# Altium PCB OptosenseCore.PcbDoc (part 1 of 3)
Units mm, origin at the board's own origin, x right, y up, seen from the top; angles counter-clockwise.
Board outline 65 x 56 mm, 4 copper layers (Top, Signal Layer 1, Power Layer 2, Bottom), stack 0.844 mm thick; 184 components, 119 nets, 728 pads, 633 vias.
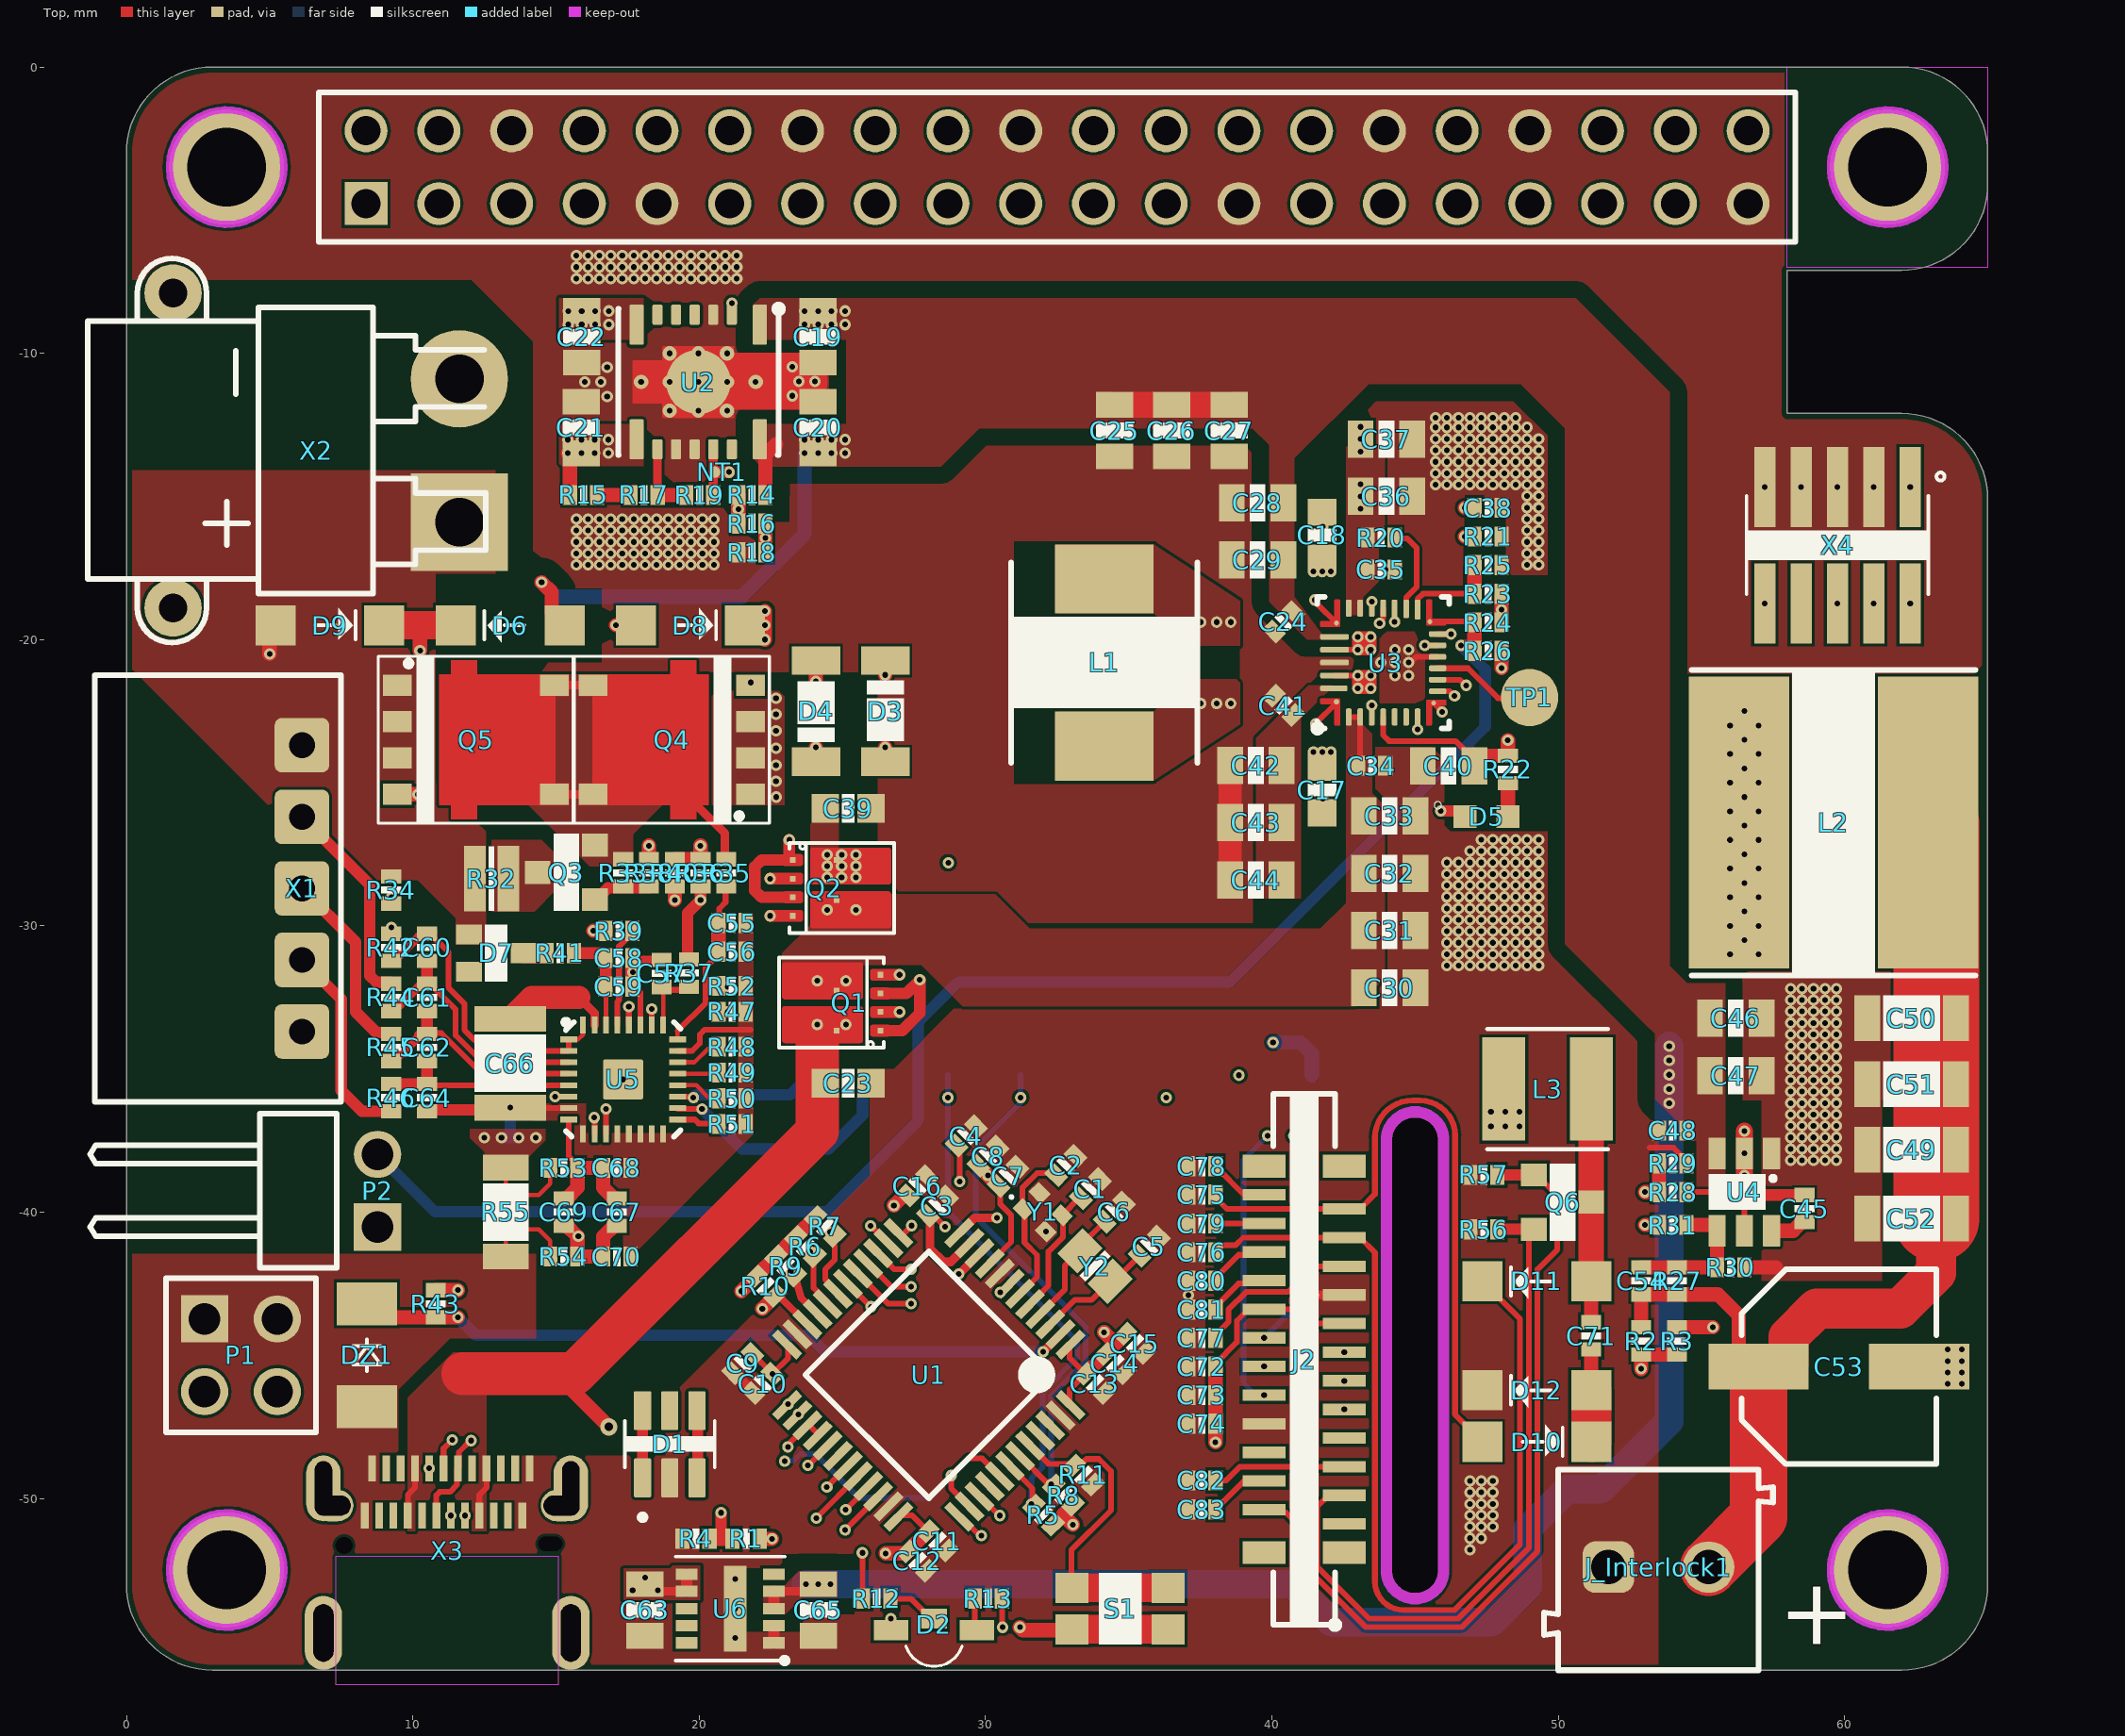
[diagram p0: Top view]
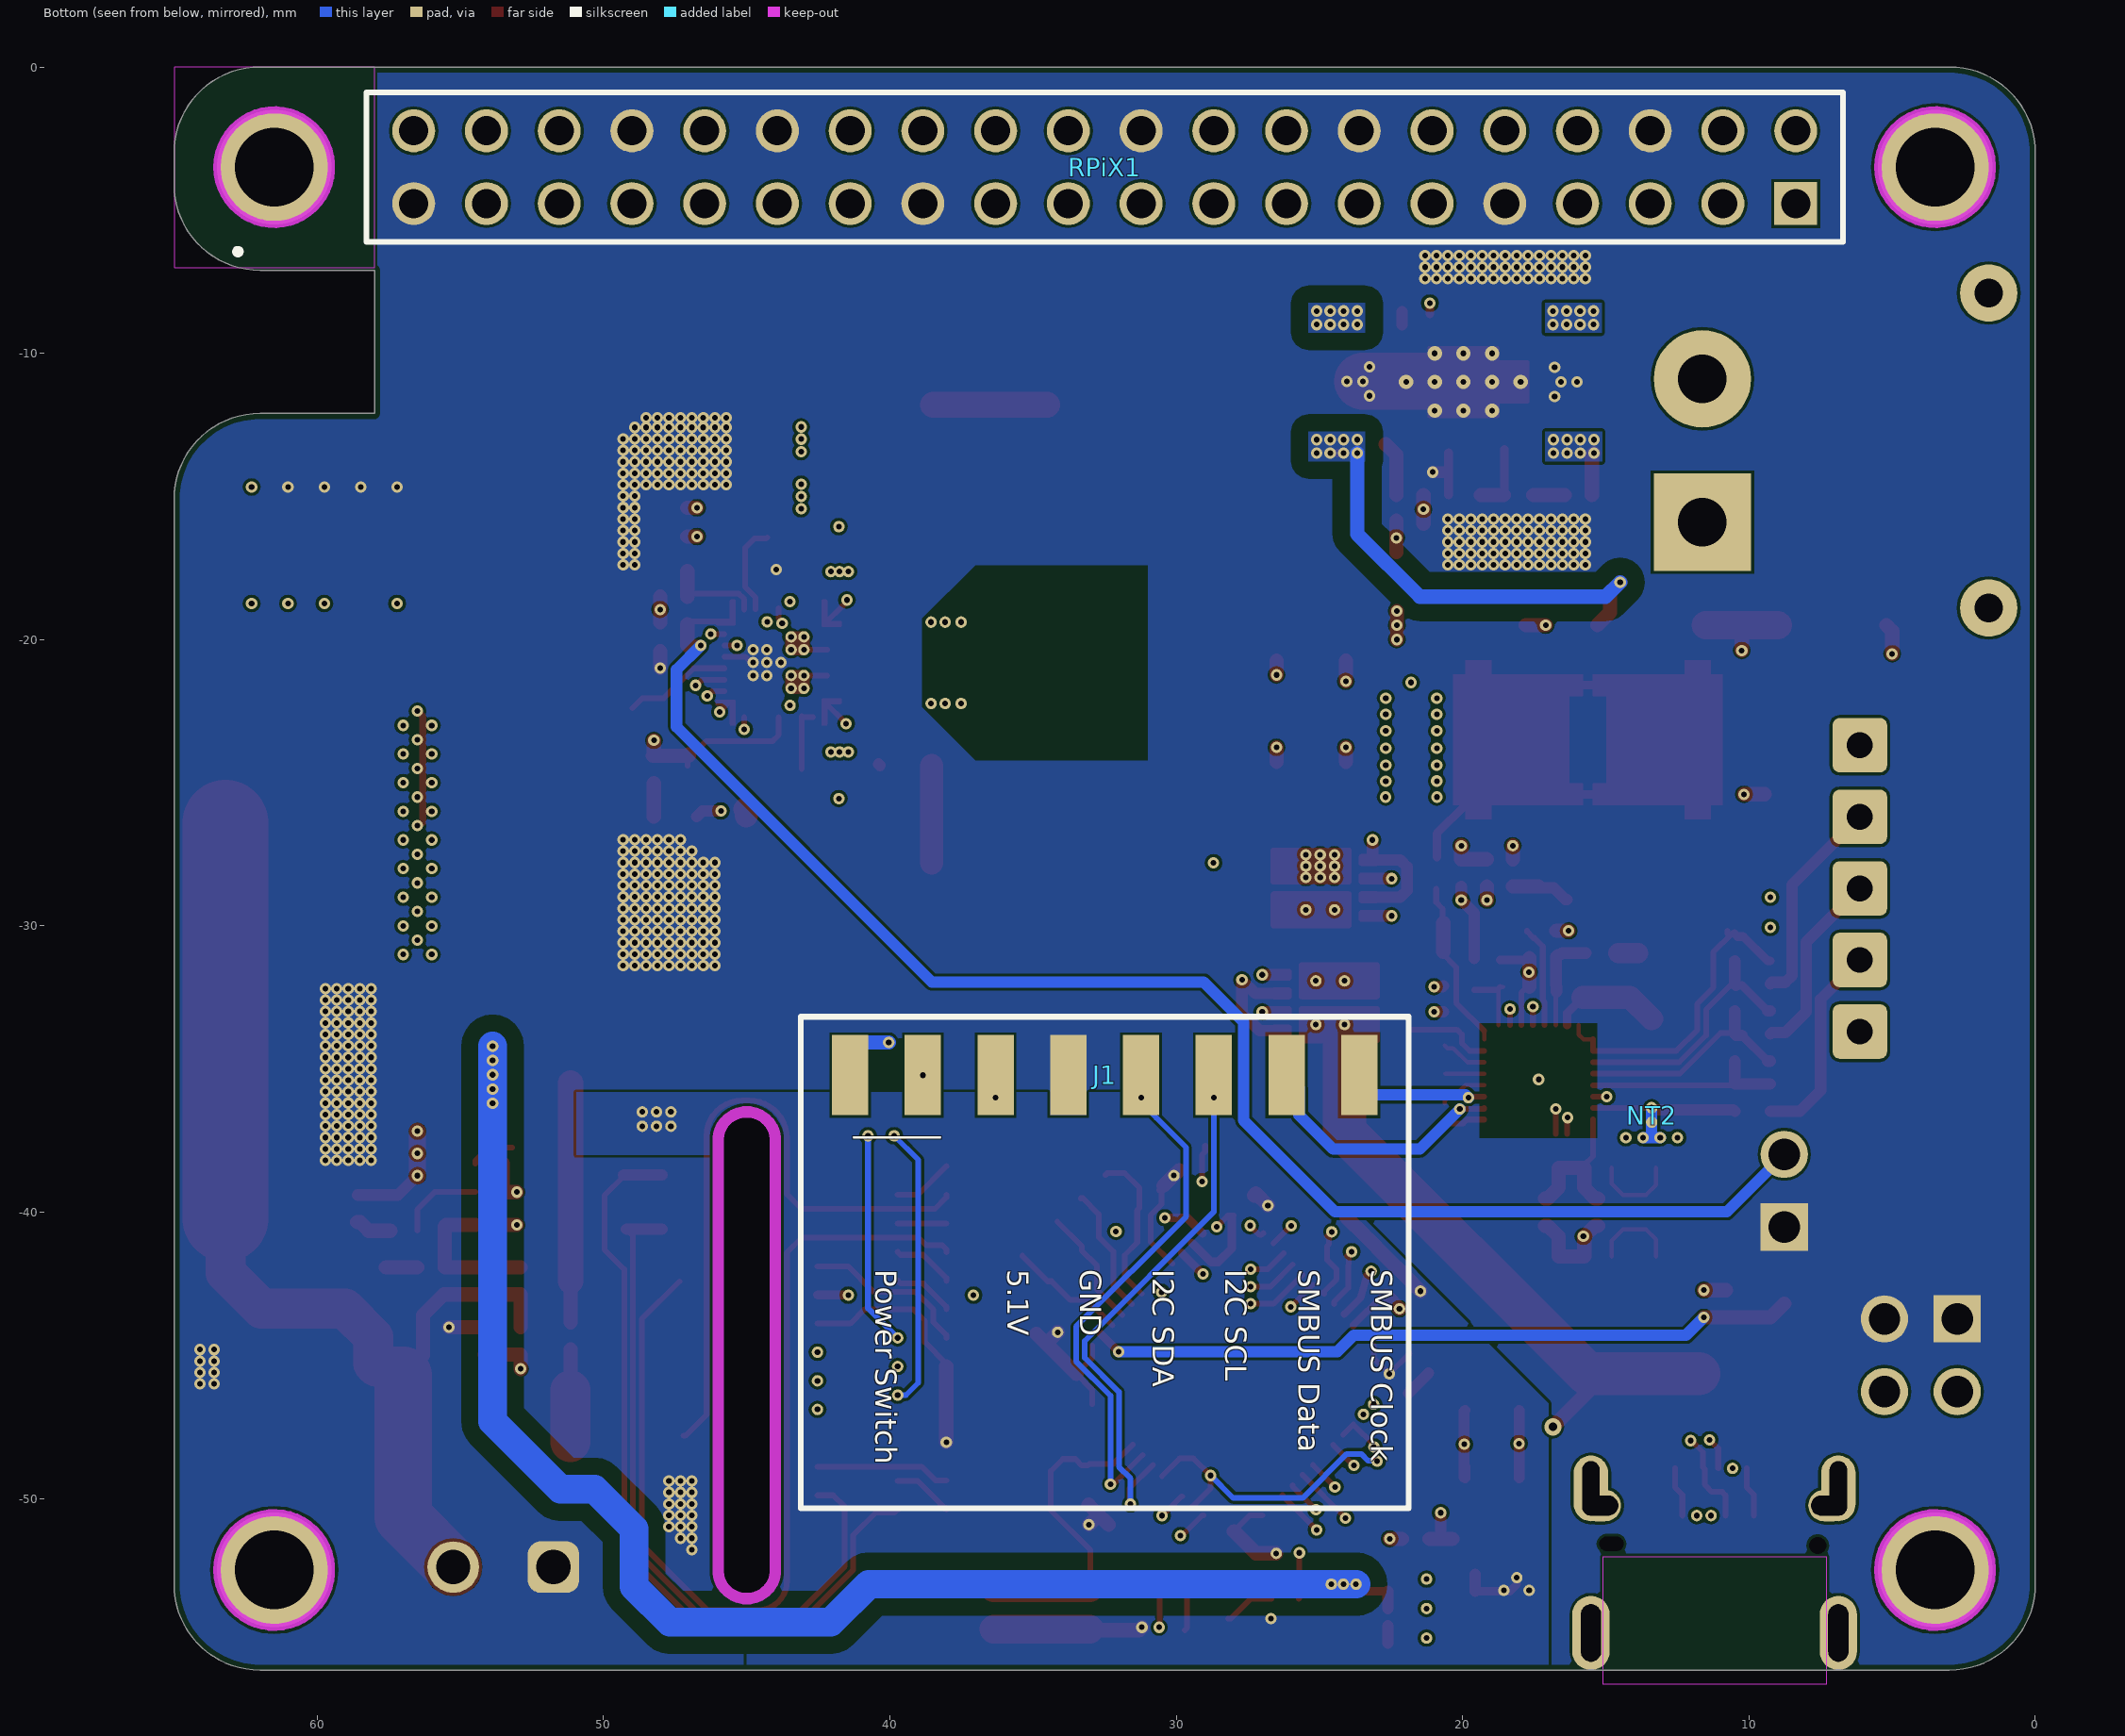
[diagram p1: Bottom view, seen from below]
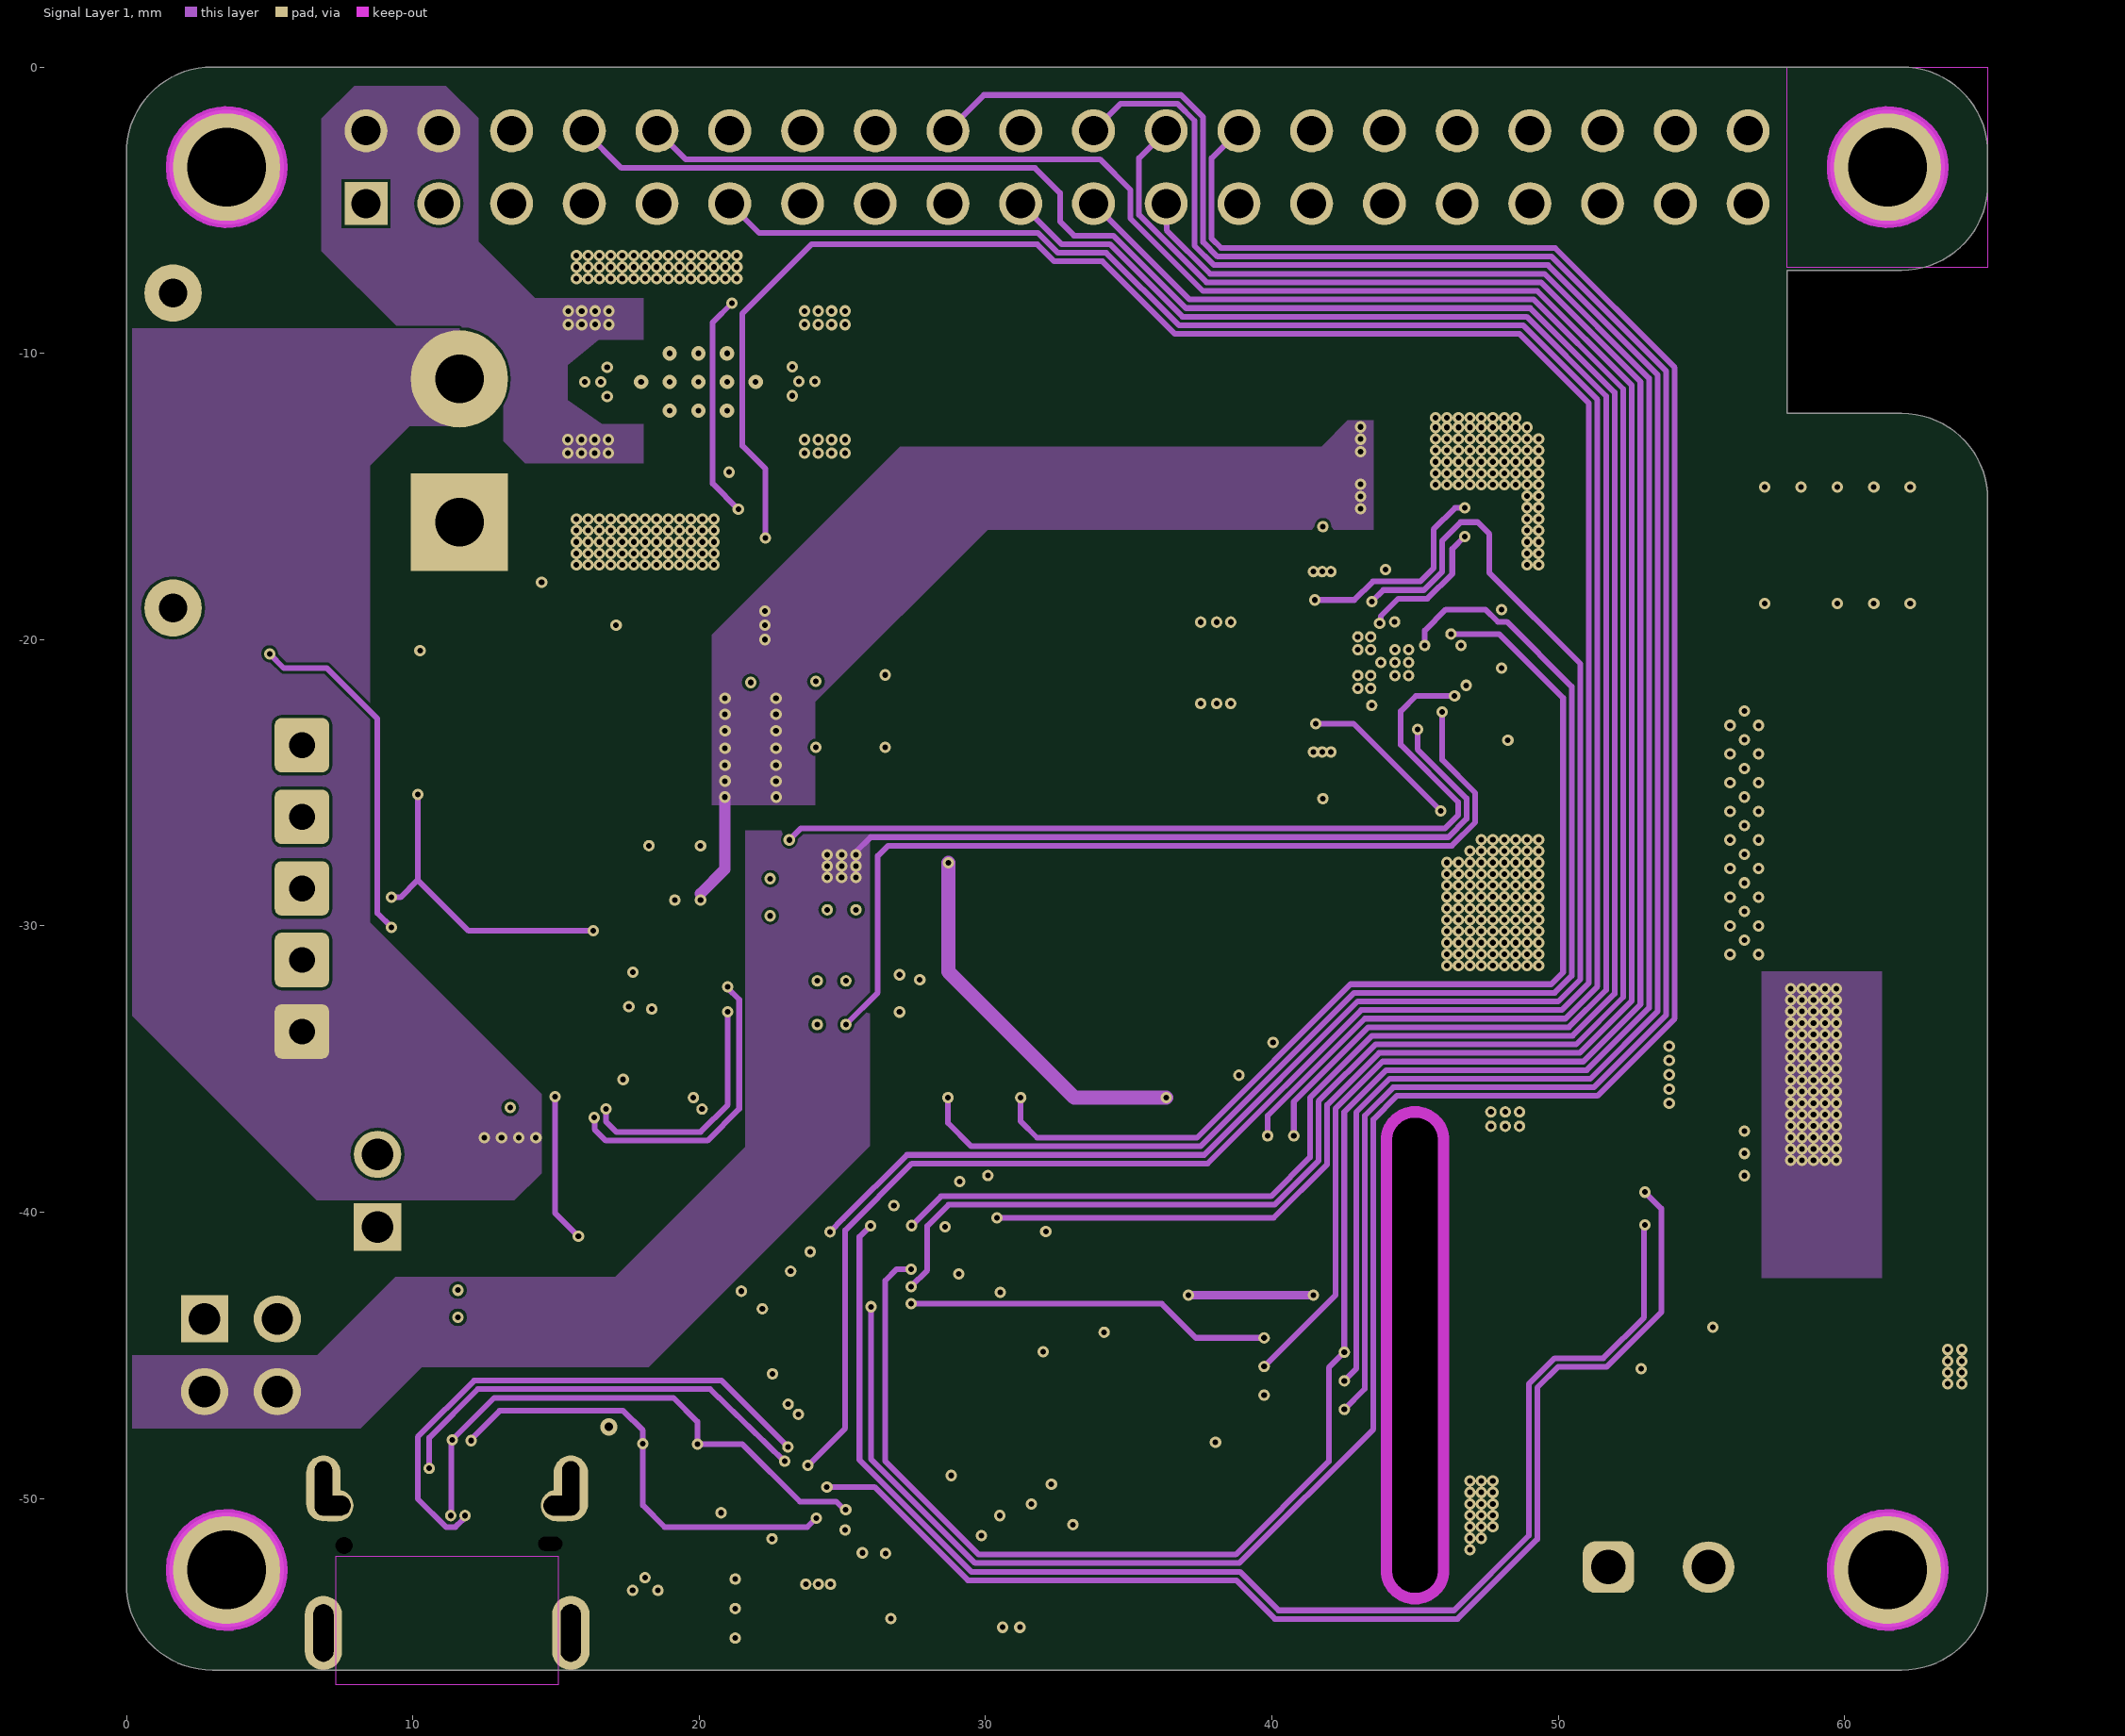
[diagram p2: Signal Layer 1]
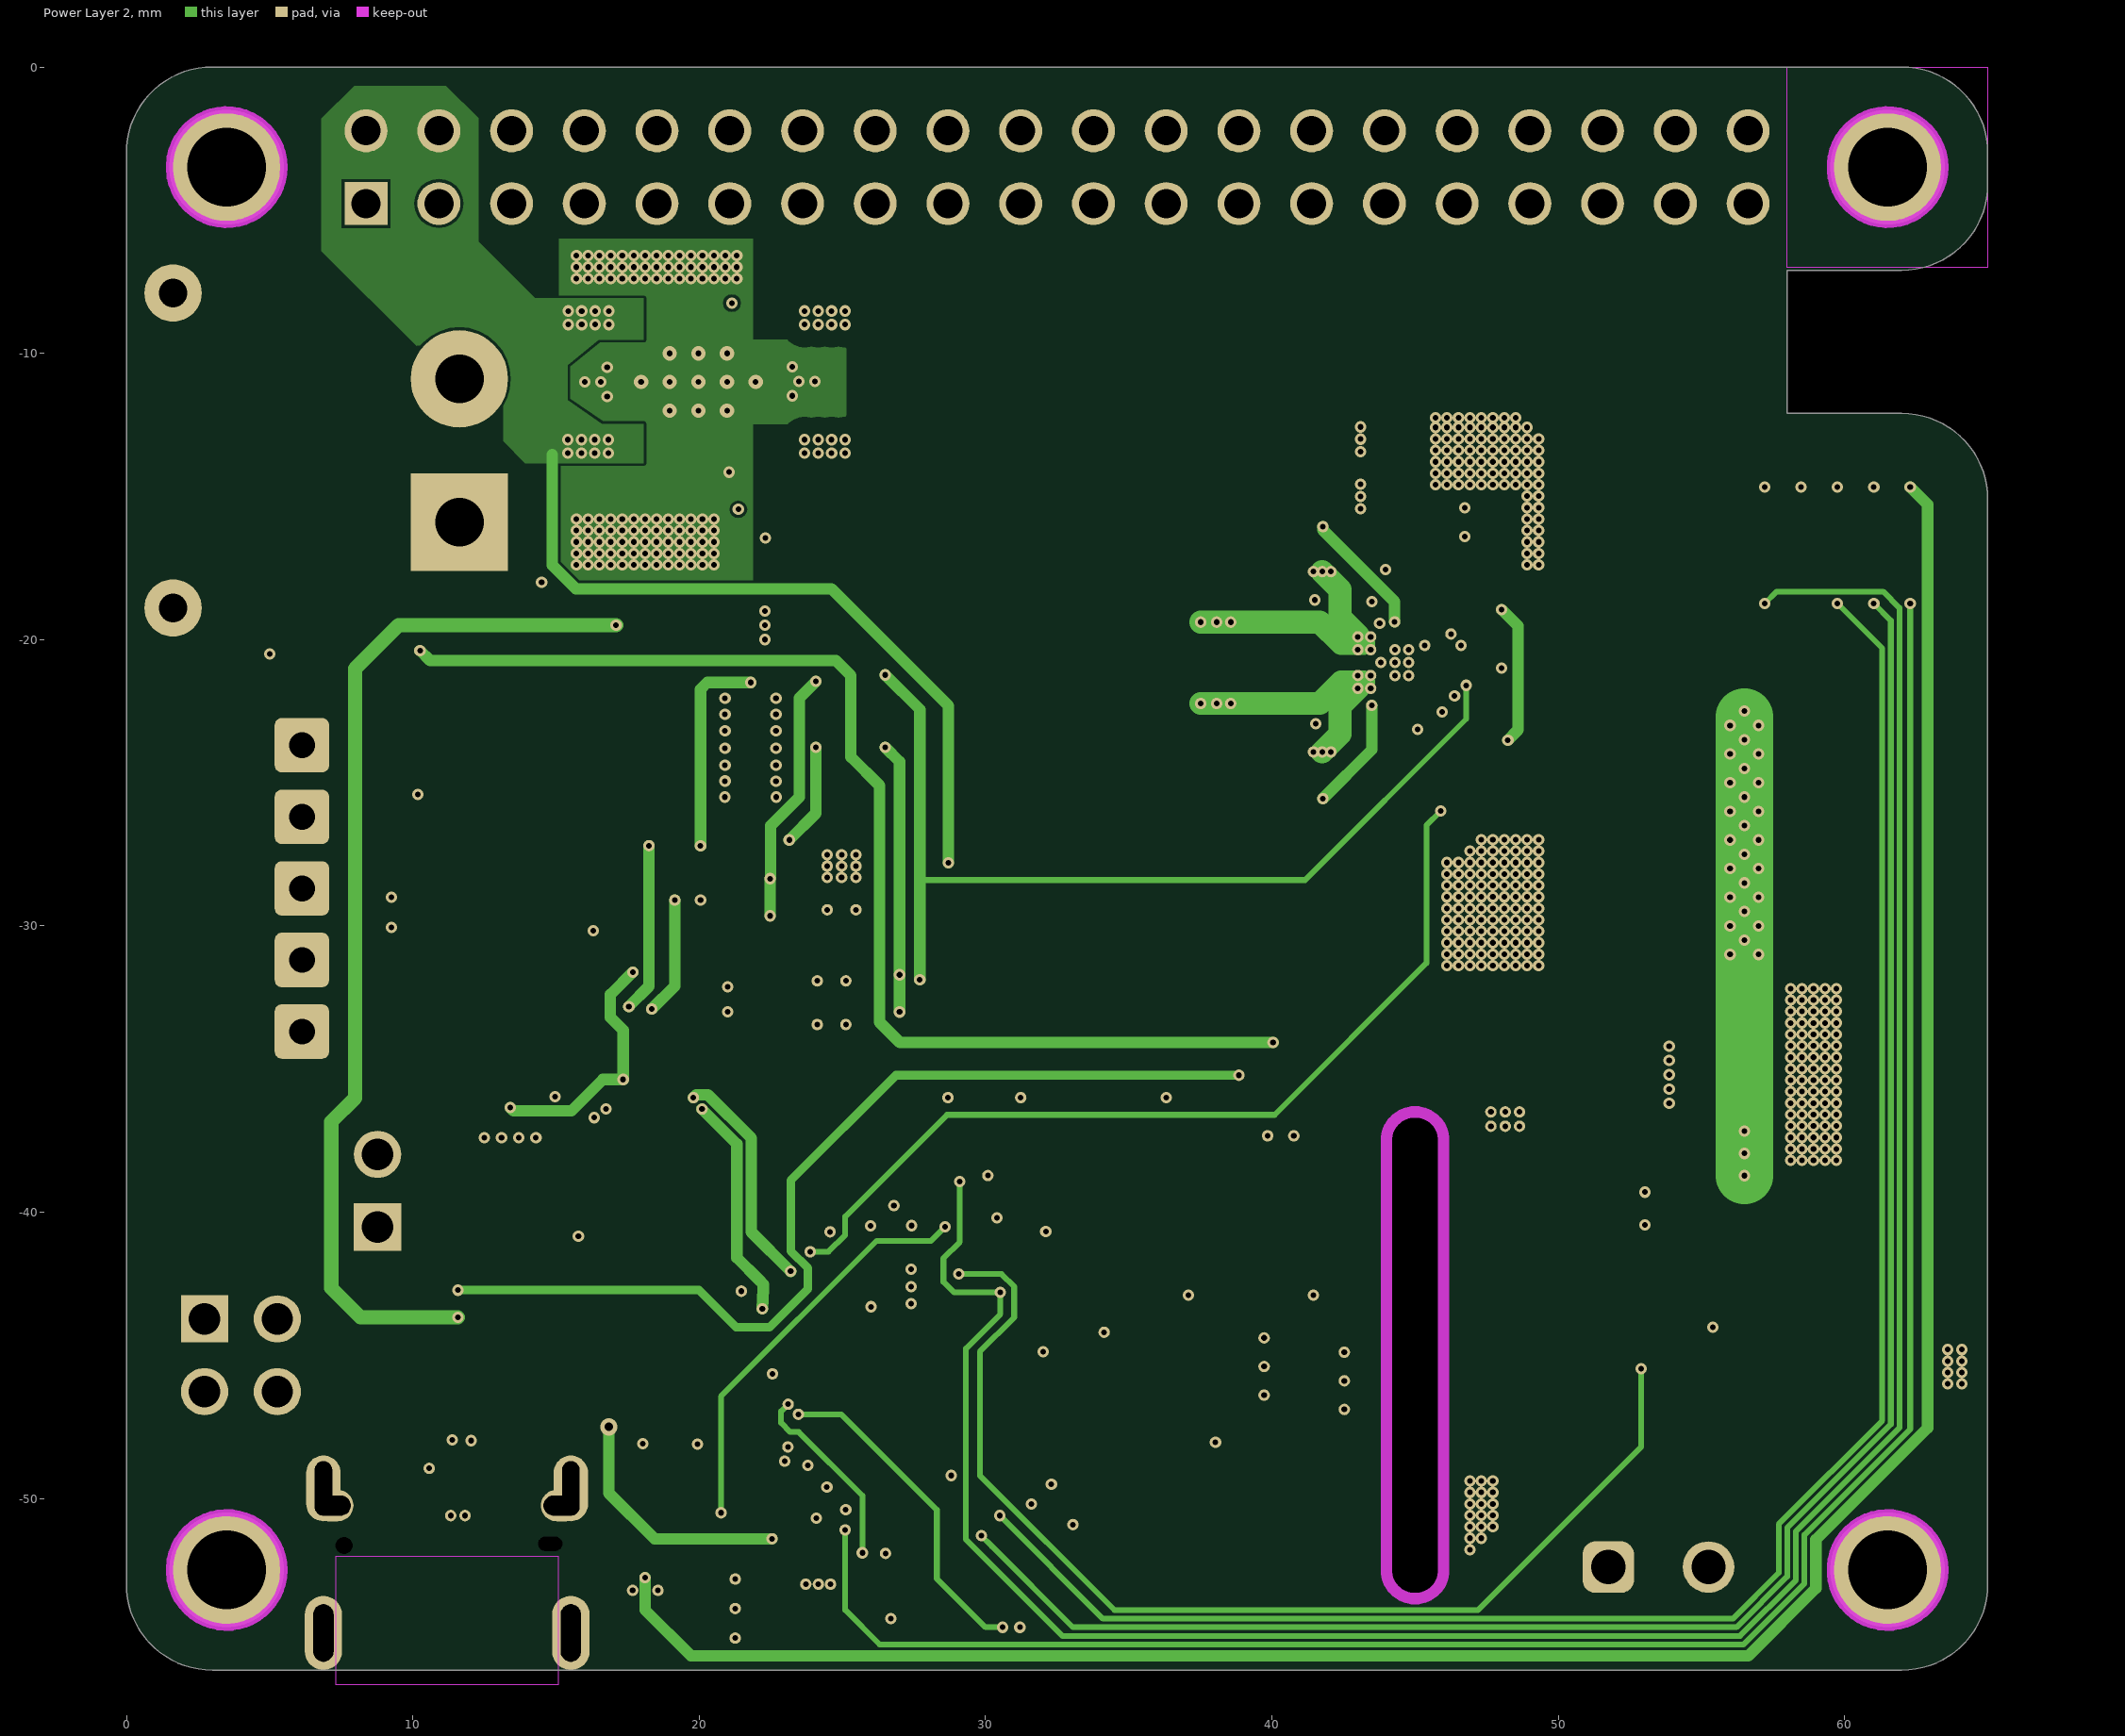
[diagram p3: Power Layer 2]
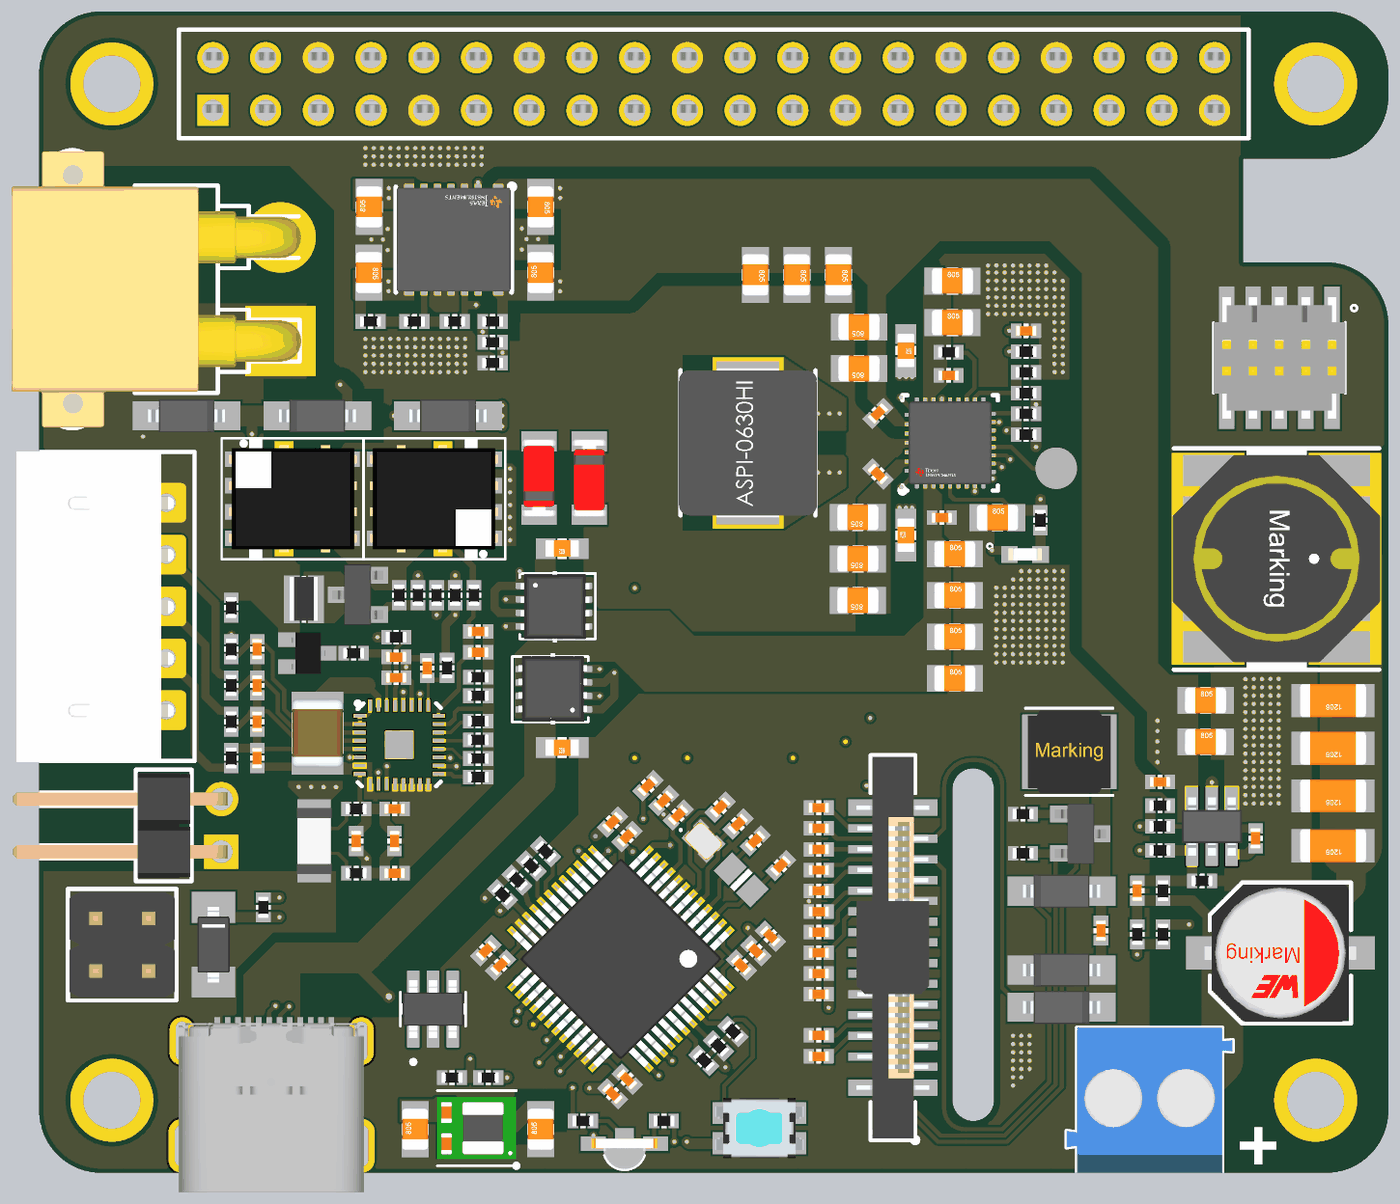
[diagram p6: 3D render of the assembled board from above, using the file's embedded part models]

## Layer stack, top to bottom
Top Solder: solder mask 0.0102, Solder Resist, Dk 3.5
Top: signal copper 0.0356
Dielectric 1: core 0.32, FR-4, Dk 4.8
Signal Layer 1: signal copper 0.036
Dielectric 3: prepreg 0.127, Dk 4.2
Power Layer 2: signal copper 0.036
Dielectric 4: core 0.254, FR-4, Dk 4.2
Bottom: signal copper 0.0356
Bottom Solder: solder mask 0.0102, Solder Resist, Dk 3.5

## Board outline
0,-53 0,-3 cw(c3,-3) 3,0 62,0 cw(c62,-3) 65,-3 65,-4.1 cw(c62,-4.1) 62,-7.1 58,-7.1 58,-12.1 62,-12.1 cw(c62,-15.1) 65,-15.1 65,-53 cw(c62,-53) 62,-56 3,-56 cw(c3,-53)
cut-out: 44,-37.5 cw(c45,-37.5) 45,-36.5 cw(c45,-37.5) 46,-37.5 46,-52.5 cw(c45,-52.5) 45,-53.5 cw(c45,-52.5) 44,-52.5

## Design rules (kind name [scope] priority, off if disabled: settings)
BoardOutlineClearance [All] p1: gap=0.2 ignorepadtopadclearanceinfootprint=FALSE
Clearance Clearance_VSYS [InPolygon vs InNet('VSYS')] p1: gap=0.6 ignorepadtopadclearanceinfootprint=FALSE
Clearance Clearance_2 [All] p2: gap=0.1 ignorepadtopadclearanceinfootprint=FALSE
Clearance Clearance_1 [All] p3: gap=0.1 ignorepadtopadclearanceinfootprint=FALSE
Clearance Clearance_KeepOut [All vs OnLayer('Keep-Out Layer')] p4 off: gap=1 ignorepadtopadclearanceinfootprint=FALSE except(0: Arc-Hole Track-Hole SMDPad-Hole THPad-Hole Via-Hole Fill-Hole Poly-Hole Region-Hole Text-Hole)
Clearance [All] p5: gap=0.1 ignorepadtopadclearanceinfootprint=FALSE
ComponentClearance [All] p1: gap=0 collisioncheckmode=3 verticalgap=0.254 showdistances=FALSE
DiffPairsRouting [All] p1: maxlimit=0.254 minlimit=0.254 mostfreqgap=0.254 toplayer_minwidth=0.381 toplayer_maxwidth=0.381 toplayer_prefwidth=0.381 midlayer1_minwidth=0.381 midlayer1_maxwidth=0.381 midlayer1_prefwidth=0.381 midlayer2_minwidth=0.381 midlayer2_maxwidth=0.381 midlayer2_prefwidth=0.381 bottomlayer_minwidth=0.381 bottomlayer_maxwidth=0.381 bottomlayer_prefwidth=0.381 maxuncoupledlength=12.7
FabricationTestPointUsage TestPointUsage [All] p1: valid=0 allowmultiple=FALSE
FabricationTestpoint Testpoint [All] p1: side=3 testpointundercomponent=TRUE minsize=1.016 maxsize=2.54 preferedsize=1.524 minholesize=0 maxholesize=1.016 preferedholesize=0.813 testpointgrid=0.025 allowsidetop=TRUE allowsidebottom=TRUE usegrid=TRUE gridtolerance=0
HoleSize [All] p1: absolutevalues=TRUE maxlimit=6 minlimit=0.2 maxpercent=80.000 minpercent=20.000
MinimumAnnularRing MinimumAnnularRing_Vias [isVia] p1: minimumring=0.1
MinimumAnnularRing [All] p2: minimumring=0.1
MinimumSolderMaskSliver [All] p1: minsoldermaskwidth=0
NetAntennae [All] p1 off: netantennaetolerance=0
PlaneConnect PlaneConnect_Vias [isVia] p1: planeconnectstyle=Direct reliefexpansion=0.508 reliefentries=4 reliefconductorwidth=0.254 reliefairgap=0.254
PlaneConnect [All] p2: planeconnectstyle=Direct reliefexpansion=0.508 reliefentries=4 reliefconductorwidth=0.254 reliefairgap=0.254
PolygonConnect PolygonConnect_Vias [isVia] p1: connectstyle=Direct reliefconductorwidth=0.254 reliefentries=4 polygonreliefangle="90 Angle" airgapwidth=0.254
PolygonConnect [All] p2: connectstyle=Direct reliefconductorwidth=0.254 reliefentries=4 polygonreliefangle="90 Angle" airgapwidth=0.254
RoutingVias [All] p1: holewidth=0.5 width=0.8 viastyle="Through Hole" minholewidth=0.2 minwidth=0.2 maxholewidth=0.8 maxwidth=1
SMDEntry [All] p1: side=TRUE corner=TRUE anyangle=TRUE
SMDToCorner [All] p1 off: distance=196850
SilkToSilkClearance [All] p1 off: silktosilkclearance=0.15
SilkToSolderMaskClearance SilkscreenOverComponentPads [IsPad] p1 off: minsilkscreentomaskgap=0.15 clearancetoexposedcopper=FALSE
SolderMaskExpansion [All] p1: expansion=0 istentingtop=FALSE
ViasUnderSMD [All] p1: allowed=FALSE
Width [All] p1: maxlimit=10 minlimit=0.15 preferedwidth=0.254 checkconnectedcopper=TRUE
20 further rules are at their usual default settings.

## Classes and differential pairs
net class USB_FS: DIFF_USB_FS_N DIFF_USB_FS_P
component class U_PowerManagement: 23 C17 C18 C19 C20 C21 C22 C23 C24 C25 C26 C27 C28 C29 C30 C31 C32 C33 C34 C35 C36 C37 C38 C39 C40 C41 C42 C43 C44 C45 C46 C47 C48 C49 C50 C51 C52 C53 C54 C55 C56 C57 C58 C59 C60 C61 C62 C63 C64 C65 C66 C67 C68 C69 C70 D3 D4 D5 D6 D7 D8 D9 DZ1 J1 L1 L2 NT1 NT2 P1 P2 Q1 Q2 Q3 Q4 Q5 R2 R3 R14 R15 R16 R17 R18 R19 R20 R21 R22 R23 R24 R25 R26 R27 R28 R29 R30 R31 R32 R33 R34 R35 R36 R37 R38 R39 R40 R41 R42 R43 R44 R45 R46 R47 R48 R49 R50 R51 R52 R53 R54 R55 TP1 U2 U3 U4 U5 U6
component class U_Microcontroller: C1 C2 C3 C4 C5 C6 C7 C8 C9 C10 C11 C12 C13 C14 C15 C16 D1 D2 R1 R4 R5 R6 R7 R8 R9 R10 R11 R12 R13 S1 U1 Y1 Y2
component class U_Connectors: C C71 C72 C73 C74 C75 C76 C77 C78 C79 C80 C81 C82 C83 D10 D11 D12 J2 J_Interlock1 L3 Q6 R56 R57 RPiX1 X1 X2 X3 X4
polygon class Direkt: NETQ4_1_L02_P018
differential pair DIFF_USB_FS: +DIFF_USB_FS_P -DIFF_USB_FS_N

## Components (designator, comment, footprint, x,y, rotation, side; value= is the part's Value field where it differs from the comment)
C1 "10pF" C_0402 33.667,-39.181 r225 top
C2 "10pF" C_0402 32.81,-38.37 r225 top
C3 "2.2uF" C_0402 28.324,-39.784 r225 top
C4 "100nF" C_0402 29.329,-37.338 r225 top
C5 "3.9pF" C_0402 35.716,-41.189 r225 top
C6 "3.9pF" C_0402 34.497,-39.995 r225 top
C7 "100nF" C_0402 30.787,-38.749 r225 top
C8 "1uF" C_0402 30.087,-38.049 r225 top
C9 "100nF" C_0402 21.524,-45.284 r45 top
C10 "1uF" C_0402 22.224,-45.984 r45 top
C11 "4.7uF" C_0402 28.324,-51.484 r135 top
C12 "2.2uF" C_0402 27.624,-52.184 r135 top
C13 "2.2uF" C_0402 33.824,-45.984 r135 top
C14 "100nF" C_0402 34.524,-45.284 r135 top
C15 "2.2uF" C_0402 35.224,-44.584 r135 top
C16 "100nF" C_0402 27.624,-39.084 r225 top
C17 "47nF" C_0603 41.756,-25.257 r90 top
C18 "47nF" C_0603 41.756,-16.352 r270 top
C19 "10uF" C_0805 24.155,-9.423 r270 top
C20 "10uF" C_0805 24.155,-12.592 r90 top
C21 "47uF" C_0805 15.887,-12.592 r270 top
C22 "47uF" C_0805 15.9,-9.423 r90 top
C23 "C_X_0603" C_0603 25.2,-35.5 r180 top
C24 "100nF" C_0402 40.411,-19.38 r45 top
C25 "10uF" C_0805 34.504,-12.7 r270 top
C26 "10uF" C_0805 36.504,-12.7 r270 top
C27 "10uF" C_0805 38.504,-12.7 r270 top
C28 "10uF" C_0805 39.5,-15.224 r180 top
C29 "10uF" C_0805 39.5,-17.224 r180 top
C30 "10uF" C_0805 44.114,-32.163 r0 top
C31 "10uF" C_0805 44.114,-30.163 r0 top
C32 "10uF" C_0805 44.114,-28.163 r0 top
C33 "10uF" C_0805 44.114,-26.163 r0 top
C34 "100nF" C_0402 43.489,-24.409 r180 top
C35 "100nF" C_0402 43.815,-17.551 r180 top
C36 "10uF" C_0805 44,-15 r0 top
C37 "10uF" C_0805 44,-13 r0 top
C38 "1nF" C_0402 47.55,-15.4 r180 top
C39 "C_X_0603" C_0603 25.2,-25.9 r180 top
C40 "4.7uF" C_0805 46.173,-24.409 r0 top
C41 "100nF" C_0402 40.411,-22.303 r315 top
C42 "10uF" C_0805 39.442,-24.397 r180 top
C43 "10uF" C_0805 39.442,-26.397 r180 top
C44 "10uF" C_0805 39.442,-28.397 r180 top
C45 "100nF" C_0402 58.6,-39.875 r90 top
C46 "10uF" C_0805 56.2,-33.227 r0 top
C47 "10uF" C_0805 56.2,-35.227 r0 top
C48 "100nF" C_0402 54,-37.15 r0 top
C49 "22uF" C_1206 62.34,-37.827 r180 top
C50 "22uF" C_1206 62.34,-33.227 r180 top
C51 "22uF" C_1206 62.34,-35.527 r180 top
C52 "22uF" C_1206 62.34,-40.227 r180 top
C53 "47uF" WCAP-ASLI_D6.3H5.5 59.8,-45.4 r180 top
C54 "75pF" C_0402 52.9,-42.4 r270 top
C55 "100pF" C_0402 21.15,-29.9 r0 top
C56 "100pF" C_0402 21.15,-30.9 r0 top
C57 "10nF" C_0402 18.689,-31.662 r270 top
C58 "100pF" C_0402 17.2,-31.125 r0 top
C59 "100pF" C_0402 17.2,-32.125 r0 top
C60 "100nF" C_0402 10.5,-30.75 r90 top
C61 "100nF" C_0402 10.5,-32.5 r90 top
C62 "100nF" C_0402 10.5,-34.25 r90 top
C63 "47uF" C_0805 18.11,-53.897 r90 top
C64 "100nF" C_0402 10.5,-36 r90 top
C65 "10uF" C_0805 24.165,-53.897 r90 top
C66 "2.2uF" C_1210 13.4,-34.8 r90 top
C67 "100pF" C_0402 17.125,-40 r270 top
C68 "100nF" C_0402 17.125,-38.45 r180 top
C69 "100nF" C_0402 15.275,-40 r270 top
C70 "100nF" C_0402 17.125,-41.55 r0 top
C71 "100nF" C_0402 51.153,-44.322 r270 top
C72 "100nF" C_0402 37.557,-45.39 r0 top
C73 "1uF" C_0402 37.557,-46.39 r0 top
C74 "2.2uF" C_0402 37.557,-47.39 r0 top
C75 "1uF" C_0402 37.557,-39.387 r0 top
C76 "1uF" C_0402 37.557,-41.4 r0 top
C77 "1uF" C_0402 37.557,-44.39 r0 top
C78 "1uF" C_0402 37.557,-38.396 r0 top
C79 "1uF" C_0402 37.557,-40.4 r0 top
C80 "1uF" C_0402 37.557,-42.4 r0 top
C81 "1uF" C_0402 37.557,-43.4 r0 top
C82 "1uF" C_0402 37.557,-49.369 r0 top
C83 "1uF" C_0402 37.557,-50.385 r0 top
D1 "USBLC6-2SC6" SOT95P280X145-6N 18.974,-48.108 r90 top
D2 "Red & Green, 120deg" WL-SBSW_1204 28.2,-55.11 r180 top
D3 "12V" MELF_SOD-80 26.5,-22.5 r90 top
D4 "12V" MELF_SOD-80 24.079,-22.5 r270 top
D5 "LTST-C190GKT" LEDM1608X80 47.498,-26.187 r0 top
D6 "MBR0530" *SOD123_MBR0530(PRIMARY) 15.4,-19.5 r0 top
D7 "BAS40WT" SOT-323 11.963,-30.951 r270 top
D8 "MBR0530" *SOD123_MBR0530(PRIMARY) 17.695,-19.5 r180 top
D9 "MBR0530" *SOD123_MBR0530(PRIMARY) 5.105,-19.5 r180 top
D10 "MBR0530" *SOD123_MBR0530(PRIMARY) 47.253,-48.022 r180 top
D11 "MBR0530" *SOD123_MBR0530(PRIMARY) 51.253,-42.422 r0 top
D12 "MBR0530" *SOD123_MBR0530(PRIMARY) 51.253,-46.222 r0 top
DZ1 "MMSZ4684" SOD-123 8.4,-45 r270 top
J1 "SAMTEC-A-TSM-108-02-L-SHJ" SAMTEC-A-TSM-108-02-L-SH 32.5,-40.5 r0 bottom locked
J2 "" 687324124422 41.13,-45.142 r90 top locked
J_Interlock1 "691103110002" 691103110002 53.5,-52.5 r0 top
L1 "2.2uH" MPXV1D0630L2R2 34.147,-20.803 r90 top
L2 "18uH" SRN1060 59.614,-26.391 r0 top
L3 "68µH, 0.45A" WE-LQS_4012 49.628,-35.7 r0 top
NT1 "NT" "NET TIE"#1 21.046,-14.152 r180 top net-tie
NT2 "NT" "NET TIE"#2 13.4,-36.86 r90 bottom net-tie
P1 "61300421121" 61300421121 4,-45 r270 top locked
P2 "61300211021" 61300211021 6,-39.25 r270 top locked
Q1 "CSD87503Q3E" CSD87503Q3E 24.8,-32.685 r180 top
Q2 "CSD87503Q3E" CSD87503Q3E 24.8,-28.677 r0 top
Q3 "DMP3098LQ-7" SOT-23-3 15.362,-28.132 r90 top
Q4 "NTMFS4C029NT1G" SO-8FL 19,-23.5 r90 top
Q5 "NTMFS4C029NT1G" SO-8FL 12.25,-23.5 r270 top
Q6 "*" SOT-23-3 50.153,-39.65 r270 top
R1 "330K" R_0402#1 21.641,-51.41 r0 top
R2 "330k" R_0402#1 52.9,-44.5 r90 top
R3 "100k" R_0402#1 54.15,-44.5 r90 top
R4 "49K9" R_0402#1 19.888,-51.41 r180 top
R5 "10k" R_0402#1 32.024,-50.584 r135 top
R6 "10k" R_0402#1 23.708,-41.2 r315 top
R7 "10k" R_0402#1 24.403,-40.505 r315 top
R8 "10k" R_0402#1 32.724,-49.884 r315 top
R9 "10k" R_0402#1 23.024,-41.884 r315 top
R10 "10k" R_0402#1 22.324,-42.584 r135 top
R11 "10k" R_0402#1 33.424,-49.184 r135 top
R12 "1k2" R_0402#1 26.2,-53.5 r0 top
R13 "1k2" R_0402#1 30.1,-53.5 r180 top
R14 "300k" R_0402#1 21.844,-14.951 r0 top
R15 "0" R_0402#1 15.962,-14.951 r180 top
R16 "0" R_0402#1 21.844,-15.951 r0 top
R17 "10k" R_0402#1 18.076,-14.951 r180 top
R18 "10k" R_0402#1 21.844,-16.951 r180 top
R19 "2k43" R_0402#1 20.019,-14.951 r180 top
R20 "100" R_0402#1 43.815,-16.438 r180 top
R21 "27k" R_0402#2 47.549,-16.4 r180 top
R22 "5k23" R_0402#1 48.242,-24.536 r90 top
R23 "137k" R_0402#1 47.55,-18.4 r0 top
R24 "5k23" R_0402#1 47.55,-19.4 r0 top
R25 "100k" R_0402#1 47.55,-17.4 r180 top
R26 "30k1" R_0402#1 47.55,-20.4 r180 top
R27 "100k" R_0402#1 54.15,-42.4 r270 top
R28 "0" R_0402#1 54,-39.3 r180 top
R29 "10k" R_0402#1 54,-38.3 r0 top
R30 "10k" R_0402#1 56.025,-41.925 r180 top
R31 "8k45" R_0402#1 54,-40.45 r0 top
R32 "100" R_0508_REVERSED 12.75,-28.35 r0 top
R33 "10M" R_0402#1 17.35,-28.15 r270 top
R34 "10M" R_0402#1 9.25,-28.75 r90 top
R35 "100" R_0402#1 20.95,-28.15 r90 top
R36 "10M" R_0402#1 20.05,-28.15 r270 top
R37 "1k2" R_0402#1 19.65,-31.65 r90 top
R38 "1k2" R_0402#1 18.25,-28.15 r270 top
R39 "1k2" R_0402#1 17.2,-30.175 r180 top
R40 "1k2" R_0402#1 19.15,-28.15 r90 top
R41 "100" R_0402#1 15.15,-30.951 r180 top
R42 "100" R_0402#1 9.25,-30.75 r270 top
R43 "1k2" R_0402#1 10.8,-43.2 r90 top
R44 "100" R_0402#1 9.25,-32.5 r270 top
R45 "100" R_0402#1 9.25,-34.25 r270 top
R46 "100" R_0402#1 9.25,-36 r90 top
R47 "10k" R_0402#1 21.15,-33 r180 top
R48 "20k" R_0402#1 21.15,-34.225 r180 top
R49 "20k" R_0402#1 21.15,-35.125 r180 top
R50 "20k" R_0402#1 21.15,-36.025 r180 top
R51 "1k2" R_0402#1 21.15,-36.925 r180 top
R52 "10k" R_0402#1 21.15,-32.1 r180 top
R53 "100" R_0402#1 15.275,-38.45 r0 top
R54 "100" R_0402#1 15.275,-41.55 r0 top
R55 "1m" R_1206 13.25,-40 r270 top
R56 "0.6R" R_0402#1 47.4,-40.6 r0 top
R57 "10k" R_0402#1 47.4,-38.7 r0 top
RPiX1 "" "RPI - POE HOLE" 32.5,-3.5 r180 bottom locked
S1 "434153017835" 434153017835 34.7,-53.847 r0 top
TP1 "TP" TESTPOINT 49.219,-22.027 r90 top
U1 "*" LQFP-48 28.024,-45.684 r225 top locked
U2 "TPSM53604RDAR" TEXAS_INSTRUMENTS_RDA0015A_MFG 19.974,-11.004 r270 top locked
U3 "BQ25792RQMR" TEXAS_INSTRUMENTS_RQM0029A_MFG 43.888,-20.805 r90 top locked
U4 "TPS54302" SOT-23-THIN 56.5,-39.3 r270 top
U5 "BQ40Z80" VQFN32 17.346,-35.366 r0 top locked
U6 "LMZM23601V3SILX" CONV_LMZM23601V3XXXX 21.085,-53.847 r180 top
X1 "B5B-XH-A" X_XH5 6.128,-28.692 r90 top locked
X2 "XT30PB-M" X_XT30_90° 6.628,-13.397 r90 top locked
X3 "10137065-00021LF" X_USBC_JACK 11.2,-51.825 r0 top locked
X4 "FTSH-105-01-L-DV-K" SAMTEC_FTSH-105-01-L-DV-K 59.751,-16.706 r180 top
Y1 "24MHz" WE-XTAL_IQXC-26 32,-40 r315 top
Y2 "*" XTAL_NX2012SA-32.768K-STD-MUB-1 33.824,-41.884 r135 top

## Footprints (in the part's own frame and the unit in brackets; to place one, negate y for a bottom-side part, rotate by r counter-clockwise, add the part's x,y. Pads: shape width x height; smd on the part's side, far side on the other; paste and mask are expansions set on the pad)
61300211021 [mm] "Pin Header, pitch 2.54 mm, THT, Angled, single row, 2p"
  rect 1.65x1.65 hole 1.1: 1(1.27,2.77)
  round 1.65 hole 1.1: 2(-1.27,2.77)
  silkscreen extent -2.69,-7.27 2.69,1.35, body extent -2.54,-7.27 2.54,3.09, height 2.58
61300421121 [mm] "Pin Header, pitch 2.54 mm, THT, Vertical, dual row, 4p"
  rect 1.65x1.65 hole 1.1: 1(-1.27,-1.27)
  round 1.65 hole 1.1: 2(-1.27,1.27) 3(1.27,-1.27) 4(1.27,1.27)
  silkscreen extent -2.69,-2.62 2.69,2.62, body extent -2.54,-2.54 2.54,2.54, height 8.59
434153017835 [mm] "Tact Switch, SMD, body 3.5x2.9mm"
  rect 1.15x1.05 smd: 1(-1.675,0.725) 2(-1.675,-0.725) 3(1.675,0.725) 4(1.675,-0.725)
  silkscreen extent -0.75,-1.25 0.75,1.25, body extent -2.15,-1.45 2.15,1.45, height 1.7
687324124422 [mm] "ZIF Connectors, Vertical, Type A, pitch 0.5mm, 24p"
  rect 0.4x1.5 smd: 1(-5.75,-1.4) 2(-5.25,1.4) 3(-4.75,-1.4) 4(-4.25,1.4) 5(-3.75,-1.4) 6(-3.25,1.4) 7(-2.75,-1.4) 8(-2.25,1.4) 9(-1.75,-1.4) 10(-1.25,1.4) 11(-0.75,-1.4) 12(-0.25,1.4) 13(0.25,-1.4) 14(0.75,1.4) 15(1.25,-1.4) 16(1.75,1.4) 17(2.25,-1.4) 18(2.75,1.4) 19(3.25,-1.4) 20(3.75,1.4) 21(4.25,-1.4) 22(4.75,1.4) 23(5.25,-1.4) 24(5.75,1.4)
  rect 0.8x1.5 smd: MP1(-6.75,-1.4) MP2(-6.75,1.4) MP3(6.75,-1.4) MP4(6.75,1.4)
  silkscreen extent -9.4,-1.2 9.28,1.07, body extent -9.2,-1.75 9.2,1.75, height 4.92
691103110002 [mm] "3,50mm - modular - blue - Horizontal wire entry - Pressure clamp - 8,4mm height - 02p"
  rrect50% 1.8x1.8 hole 1.2: 1(-1.75,0.1)
  round 1.8 hole 1.2: 2(1.75,0.1)
  silkscreen extent -4,-3.5 4,3.5, body extent -4,-3.5 4,3.5, height 8.45
*SOD123_MBR0530(PRIMARY) [mm]
  rect 1.4x1.4 smd: A(-0.1,0) C(-3.9,0)
  silkscreen extent -2.9,-0.6 -1.5,0.5, body extent -3.85,-0.8 -0.15,0.8, height 1.35
C_0402 [mm]
  rect 0.5x0.7 smd: 1(-0.475,0) 2(0.475,0)
  silkscreen extent -0.13,-0.35 0.12,0.35, body extent -0.5,-0.25 0.5,0.25, height 0.5
C_0603 [mm]
  rect 0.95x1 smd: 1(-0.8,0) 2(0.8,0)
  silkscreen extent -0.23,-0.5 0.23,0.5, body extent -0.8,-0.4 0.8,0.4, height 0.3
C_0805 [mm]
  rect 0.9x1.3 smd: 1(-0.9,0) 2(0.9,0)
  silkscreen extent -0.28,-0.65 0.28,0.65, body extent -1,-0.62 1,0.62, height 0.78
C_1206 [mm]
  rect 0.9x1.6 smd: 1(-1.55,0) 2(1.55,0)
  silkscreen extent -1,-0.8 1,0.8, body extent -1.6,-0.8 1.6,0.8, height 1
C_1210 [mm]
  rect 0.9x2.5 smd: 1(-1.55,0) 2(1.55,0)
  silkscreen extent -1,-1.25 1,1.25, body extent -1.65,-1.25 1.65,1.25, height 2.79
CONV_LMZM23601V3XXXX [mm]
  rect 0.75x0.4 smd paste-0.1 mask+0: 1(-1.525,1.2) 2(-1.525,0.6) 3(-1.525,0) 4(-1.525,-0.6) 5(-1.525,-1.2) 6(1.525,-1.2) 7(1.525,-0.6) 8(1.525,0) 9(1.525,0.6) 10(1.525,1.2)
  rect 0.8x3 smd paste-0.25 mask+0: 11(-0.175,0)
  round 0.4 hole 0.2 mask+0: 11_1(-0.175,1.03) 11_2(-0.175,0) 11_3(-0.175,-1.03)
  silkscreen extent -2,-1.81 1.9,1.91, body extent -1.9,-1.5 1.9,1.5, height 1.58
CSD87503Q3E [mm]
  rect 0.2x0.2 smd paste-1 mask+0: 1(-1.535,0.975) 2(-1.535,0.325) 3(-1.535,-0.325) 4(-1.535,-0.975) 9(0,0.975) 10(0,-0.425)
  round 0.4 hole 0.2 mask+0: 9.1(-0.325,0.763) 9.2(0.675,0.763) 10.1(-0.325,-0.763) 10.2(0.675,-0.763)
  Top region: -1.265,-0.125 -1.26,-0.126 -1.254,-0.126 -1.249,-0.127 -1.244,-0.128 -1.239,-0.13 -1.234,-0.132 -1.229,-0.134 -1.225,-0.136 -1.22,-0.138 -1.216,-0.141 -1.211,-0.144 -1.207,-0.147 -1.203,-0.151 -1.199,-0.154 -1.196,-0.158 -1.192,-0.162 -1.189,-0.166 -1.186,-0.171 -1.183,-0.175 -1.181,-0.18 -1.179,-0.184 -1.177,-0.189 -1.175,-0.194 -1.173,-0.199 -1.172,-0.204 -1.171,-0.209 -1.171,-0.215 -1.17,-0.22 -1.17,-0.225 -1.17,-0.425 -1.17,-0.43 -1.171,-0.435 -1.171,-0.441 -1.172,-0.446 -1.173,-0.451 -1.175,-0.456 -1.177,-0.461 -1.179,-0.466 -1.181,-0.47 -1.183,-0.475 -1.186,-0.479 -1.189,-0.484 -1.192,-0.488 -1.196,-0.492 -1.199,-0.496 -1.203,-0.499 -1.207,-0.503 -1.211,-0.506 -1.216,-0.509 -1.22,-0.512 -1.225,-0.514 -1.229,-0.516 -1.234,-0.518 -1.239,-0.52 -1.244,-0.522 -1.249,-0.523 -1.254,-0.524 -1.26,-0.524 -1.265,-0.525 -1.27,-0.525 -1.8,-0.525 -1.805,-0.525 -1.81,-0.524 -1.816,-0.524 -1.821,-0.523 -1.826,-0.522 -1.831,-0.52 -1.836,-0.518 -1.841,-0.516 -1.845,-0.514 -1.85,-0.512 -1.854,-0.509 -1.859,-0.506 -1.863,-0.503 -1.867,-0.499 -1.871,-0.496 -1.874,-0.492 -1.878,-0.488 -1.881,-0.484 -1.884,-0.479 -1.887,-0.475 -1.889,-0.47 -1.891,-0.466 -1.893,-0.461 -1.895,-0.456 -1.897,-0.451 -1.898,-0.446 -1.899,-0.441 -1.899,-0.435 -1.9,-0.43 -1.9,-0.425 -1.9,-0.225 -1.9,-0.22 -1.899,-0.215 -1.899,-0.209 -1.898,-0.204 -1.897,-0.199 -1.895,-0.194 -1.893,-0.189 -1.891,-0.184 -1.889,-0.18 -1.887,-0.175 -1.884,-0.171 -1.881,-0.166 -1.878,-0.162 -1.874,-0.158 -1.871,-0.154 -1.867,-0.151 -1.863,-0.147 -1.859,-0.144 -1.854,-0.141 -1.85,-0.138 -1.845,-0.136 -1.841,-0.134 -1.836,-0.132 -1.831,-0.13 -1.826,-0.128 -1.821,-0.127 -1.816,-0.126 -1.81,-0.126 -1.805,-0.125 -1.8,-0.125 -1.27,-0.125
  Top region: -1.265,0.525 -1.26,0.524 -1.254,0.524 -1.249,0.523 -1.244,0.522 -1.239,0.52 -1.234,0.518 -1.229,0.516 -1.225,0.514 -1.22,0.512 -1.216,0.509 -1.211,0.506 -1.207,0.503 -1.203,0.499 -1.199,0.496 -1.196,0.492 -1.192,0.488 -1.189,0.484 -1.186,0.479 -1.183,0.475 -1.181,0.47 -1.179,0.466 -1.177,0.461 -1.175,0.456 -1.173,0.451 -1.172,0.446 -1.171,0.441 -1.171,0.435 -1.17,0.43 -1.17,0.425 -1.17,0.225 -1.17,0.22 -1.171,0.215 -1.171,0.209 -1.172,0.204 -1.173,0.199 -1.175,0.194 -1.177,0.189 -1.179,0.184 -1.181,0.18 -1.183,0.175 -1.186,0.171 -1.189,0.166 -1.192,0.162 -1.196,0.158 -1.199,0.154 -1.203,0.151 -1.207,0.147 -1.211,0.144 -1.216,0.141 -1.22,0.138 -1.225,0.136 -1.229,0.134 -1.234,0.132 -1.239,0.13 -1.244,0.128 -1.249,0.127 -1.254,0.126 -1.26,0.126 -1.265,0.125 -1.27,0.125 -1.8,0.125 -1.805,0.125 -1.81,0.126 -1.816,0.126 -1.821,0.127 -1.826,0.128 -1.831,0.13 -1.836,0.132 -1.841,0.134 -1.845,0.136 -1.85,0.138 -1.854,0.141 -1.859,0.144 -1.863,0.147 -1.867,0.151 -1.871,0.154 -1.874,0.158 -1.878,0.162 -1.881,0.166 -1.884,0.171 -1.887,0.175 -1.889,0.18 -1.891,0.184 -1.893,0.189 -1.895,0.194 -1.897,0.199 -1.898,0.204 -1.899,0.209 -1.899,0.215 -1.9,0.22 -1.9,0.225 -1.9,0.425 -1.9,0.43 -1.899,0.435 -1.899,0.441 -1.898,0.446 -1.897,0.451 -1.895,0.456 -1.893,0.461 -1.891,0.466 -1.889,0.47 -1.887,0.475 -1.884,0.479 -1.881,0.484 -1.878,0.488 -1.874,0.492 -1.871,0.496 -1.867,0.499 -1.863,0.503 -1.859,0.506 -1.854,0.509 -1.85,0.512 -1.845,0.514 -1.841,0.516 -1.836,0.518 -1.831,0.52 -1.826,0.522 -1.821,0.523 -1.816,0.524 -1.81,0.524 -1.805,0.525 -1.8,0.525 -1.27,0.525
  Top region: -1.265,1.175 -1.26,1.174 -1.254,1.174 -1.249,1.173 -1.244,1.172 -1.239,1.17 -1.234,1.168 -1.229,1.166 -1.225,1.164 -1.22,1.162 -1.216,1.159 -1.211,1.156 -1.207,1.153 -1.203,1.149 -1.199,1.146 -1.196,1.142 -1.192,1.138 -1.189,1.134 -1.186,1.129 -1.183,1.125 -1.181,1.12 -1.179,1.116 -1.177,1.111 -1.175,1.106 -1.173,1.101 -1.172,1.096 -1.171,1.091 -1.171,1.085 -1.17,1.08 -1.17,1.075 -1.17,0.875 -1.17,0.87 -1.171,0.865 -1.171,0.859 -1.172,0.854 -1.173,0.849 -1.175,0.844 -1.177,0.839 -1.179,0.834 -1.181,0.83 -1.183,0.825 -1.186,0.821 -1.189,0.816 -1.192,0.812 -1.196,0.808 -1.199,0.804 -1.203,0.801 -1.207,0.797 -1.211,0.794 -1.216,0.791 -1.22,0.788 -1.225,0.786 -1.229,0.784 -1.234,0.782 -1.239,0.78 -1.244,0.778 -1.249,0.777 -1.254,0.776 -1.26,0.776 -1.265,0.775 -1.27,0.775 -1.8,0.775 -1.805,0.775 -1.81,0.776 -1.816,0.776 -1.821,0.777 -1.826,0.778 -1.831,0.78 -1.836,0.782 -1.841,0.784 -1.845,0.786 -1.85,0.788 -1.854,0.791 -1.859,0.794 -1.863,0.797 -1.867,0.801 -1.871,0.804 -1.874,0.808 -1.878,0.812 -1.881,0.816 -1.884,0.821 -1.887,0.825 -1.889,0.83 -1.891,0.834 -1.893,0.839 -1.895,0.844 -1.897,0.849 -1.898,0.854 -1.899,0.859 -1.899,0.865 -1.9,0.87 -1.9,0.875 -1.9,1.075 -1.9,1.08 -1.899,1.085 -1.899,1.091 -1.898,1.096 -1.897,1.101 -1.895,1.106 -1.893,1.111 -1.891,1.116 -1.889,1.12 -1.887,1.125 -1.884,1.129 -1.881,1.134 -1.878,1.138 -1.874,1.142 -1.871,1.146 -1.867,1.149 -1.863,1.153 -1.859,1.156 -1.854,1.159 -1.85,1.162 -1.845,1.164 -1.841,1.166 -1.836,1.168 -1.831,1.17 -1.826,1.172 -1.821,1.173 -1.816,1.174 -1.81,1.174 -1.805,1.175 -1.8,1.175 -1.27,1.175
  Top region: -1.265,-0.775 -1.26,-0.776 -1.254,-0.776 -1.249,-0.777 -1.244,-0.778 -1.239,-0.78 -1.234,-0.782 -1.229,-0.784 -1.225,-0.786 -1.22,-0.788 -1.216,-0.791 -1.211,-0.794 -1.207,-0.797 -1.203,-0.801 -1.199,-0.804 -1.196,-0.808 -1.192,-0.812 -1.189,-0.816 -1.186,-0.821 -1.183,-0.825 -1.181,-0.83 -1.179,-0.834 -1.177,-0.839 -1.175,-0.844 -1.173,-0.849 -1.172,-0.854 -1.171,-0.859 -1.171,-0.865 -1.17,-0.87 -1.17,-0.875 -1.17,-1.075 -1.17,-1.08 -1.171,-1.085 -1.171,-1.091 -1.172,-1.096 -1.173,-1.101 -1.175,-1.106 -1.177,-1.111 -1.179,-1.116 -1.181,-1.12 -1.183,-1.125 -1.186,-1.129 -1.189,-1.134 -1.192,-1.138 -1.196,-1.142 -1.199,-1.146 -1.203,-1.149 -1.207,-1.153 -1.211,-1.156 -1.216,-1.159 -1.22,-1.162 -1.225,-1.164 -1.229,-1.166 -1.234,-1.168 -1.239,-1.17 -1.244,-1.172 -1.249,-1.173 -1.254,-1.174 -1.26,-1.174 -1.265,-1.175 -1.27,-1.175 -1.8,-1.175 -1.805,-1.175 -1.81,-1.174 -1.816,-1.174 -1.821,-1.173 -1.826,-1.172 -1.831,-1.17 -1.836,-1.168 -1.841,-1.166 -1.845,-1.164 -1.85,-1.162 -1.854,-1.159 -1.859,-1.156 -1.863,-1.153 -1.867,-1.149 -1.871,-1.146 -1.874,-1.142 -1.878,-1.138 -1.881,-1.134 -1.884,-1.129 -1.887,-1.125 -1.889,-1.12 -1.891,-1.116 -1.893,-1.111 -1.895,-1.106 -1.897,-1.101 -1.898,-1.096 -1.899,-1.091 -1.899,-1.085 -1.9,-1.08 -1.9,-1.075 -1.9,-0.875 -1.9,-0.87 -1.899,-0.865 -1.899,-0.859 -1.898,-0.854 -1.897,-0.849 -1.895,-0.844 -1.893,-0.839 -1.891,-0.834 -1.889,-0.83 -1.887,-0.825 -1.884,-0.821 -1.881,-0.816 -1.878,-0.812 -1.874,-0.808 -1.871,-0.804 -1.867,-0.801 -1.863,-0.797 -1.859,-0.794 -1.854,-0.791 -1.85,-0.788 -1.845,-0.786 -1.841,-0.784 -1.836,-0.782 -1.831,-0.78 -1.826,-0.778 -1.821,-0.777 -1.816,-0.776 -1.81,-0.776 -1.805,-0.775 -1.8,-0.775 -1.27,-0.775
  Top region: 1.805,1.405 1.81,1.404 1.816,1.404 1.821,1.403 1.826,1.402 1.831,1.4 1.836,1.398 1.841,1.396 1.845,1.394 1.85,1.392 1.854,1.389 1.859,1.386 1.863,1.383 1.867,1.379 1.871,1.376 1.874,1.372 1.878,1.368 1.881,1.364 1.884,1.359 1.887,1.355 1.889,1.35 1.891,1.346 1.893,1.341 1.895,1.336 1.897,1.331 1.898,1.326 1.899,1.321 1.899,1.315 1.9,1.31 1.9,1.305 1.9,0.225 1.9,0.22 1.899,0.215 1.899,0.209 1.898,0.204 1.897,0.199 1.895,0.194 1.893,0.189 1.891,0.184 1.889,0.18 1.887,0.175 1.884,0.171 1.881,0.166 1.878,0.162 1.874,0.158 1.871,0.154 1.867,0.151 1.863,0.147 1.859,0.144 1.854,0.141 1.85,0.138 1.845,0.136 1.841,0.134 1.836,0.132 1.831,0.13 1.826,0.128 1.821,0.127 1.816,0.126 1.81,0.126 1.805,0.125 1.8,0.125 -0.82,0.125 -0.825,0.125 -0.83,0.126 -0.836,0.126 -0.841,0.127 -0.846,0.128 -0.851,0.13 -0.856,0.132 -0.861,0.134 -0.865,0.136 -0.87,0.138 -0.874,0.141 -0.879,0.144 -0.883,0.147 -0.887,0.151 -0.891,0.154 -0.894,0.158 -0.898,0.162 -0.901,0.166 -0.904,0.171 -0.907,0.175 -0.909,0.18 -0.911,0.184 -0.913,0.189 -0.915,0.194 -0.917,0.199 -0.918,0.204 -0.919,0.209 -0.919,0.215 -0.92,0.22 -0.92,0.225 -0.92,1.305 -0.92,1.31 -0.919,1.315 -0.919,1.321 -0.918,1.326 -0.917,1.331 -0.915,1.336 -0.913,1.341 -0.911,1.346 -0.909,1.35 -0.907,1.355 -0.904,1.359 -0.901,1.364 -0.898,1.368 -0.894,1.372 -0.891,1.376 -0.887,1.379 -0.883,1.383 -0.879,1.386 -0.874,1.389 -0.87,1.392 -0.865,1.394 -0.861,1.396 -0.856,1.398 -0.851,1.4 -0.846,1.402 -0.841,1.403 -0.836,1.404 -0.83,1.404 -0.825,1.405 -0.82,1.405 1.8,1.405
  Top region: 1.805,-0.125 1.81,-0.126 1.816,-0.126 1.821,-0.127 1.826,-0.128 1.831,-0.13 1.836,-0.132 1.841,-0.134 1.845,-0.136 1.85,-0.138 1.854,-0.141 1.859,-0.144 1.863,-0.147 1.867,-0.151 1.871,-0.154 1.874,-0.158 1.878,-0.162 1.881,-0.166 1.884,-0.171 1.887,-0.175 1.889,-0.18 1.891,-0.184 1.893,-0.189 1.895,-0.194 1.897,-0.199 1.898,-0.204 1.899,-0.209 1.899,-0.215 1.9,-0.22 1.9,-0.225 1.9,-1.305 1.9,-1.31 1.899,-1.315 1.899,-1.321 1.898,-1.326 1.897,-1.331 1.895,-1.336 1.893,-1.341 1.891,-1.346 1.889,-1.35 1.887,-1.355 1.884,-1.359 1.881,-1.364 1.878,-1.368 1.874,-1.372 1.871,-1.376 1.867,-1.379 1.863,-1.383 1.859,-1.386 1.854,-1.389 1.85,-1.392 1.845,-1.394 1.841,-1.396 1.836,-1.398 1.831,-1.4 1.826,-1.402 1.821,-1.403 1.816,-1.404 1.81,-1.404 1.805,-1.405 1.8,-1.405 -0.82,-1.405 -0.825,-1.405 -0.83,-1.404 -0.836,-1.404 -0.841,-1.403 -0.846,-1.402 -0.851,-1.4 -0.856,-1.398 -0.861,-1.396 -0.865,-1.394 -0.87,-1.392 -0.874,-1.389 -0.879,-1.386 -0.883,-1.383 -0.887,-1.379 -0.891,-1.376 -0.894,-1.372 -0.898,-1.368 -0.901,-1.364 -0.904,-1.359 -0.907,-1.355 -0.909,-1.35 -0.911,-1.346 -0.913,-1.341 -0.915,-1.336 -0.917,-1.331 -0.918,-1.326 -0.919,-1.321 -0.919,-1.315 -0.92,-1.31 -0.92,-1.305 -0.92,-0.225 -0.92,-0.22 -0.919,-0.215 -0.919,-0.209 -0.918,-0.204 -0.917,-0.199 -0.915,-0.194 -0.913,-0.189 -0.911,-0.184 -0.909,-0.18 -0.907,-0.175 -0.904,-0.171 -0.901,-0.166 -0.898,-0.162 -0.894,-0.158 -0.891,-0.154 -0.887,-0.151 -0.883,-0.147 -0.879,-0.144 -0.874,-0.141 -0.87,-0.138 -0.865,-0.136 -0.861,-0.134 -0.856,-0.132 -0.851,-0.13 -0.846,-0.128 -0.841,-0.127 -0.836,-0.126 -0.83,-0.126 -0.825,-0.125 -0.82,-0.125 1.8,-0.125
  silkscreen extent -1.65,-1.57 2.01,1.61, body extent -1.6,-1.75 1.7,1.7, height 0.9
LEDM1608X80 [mm]
  rect 0.8x0.8 smd: A(0.75,0) C(-0.75,0)
  silkscreen extent -1.83,0.27 -1.57,0.53, body extent -0.8,-0.3 0.8,0.3, height 1.15
LQFP-48 [mm] "LQFP-48, 48-Leads, Body 6,90x6,90mm, Pitch 0,50mm, IPC Medium Density"
  rect 1.2x0.3 smd paste-0.1: 1(-4.25,2.75) 2(-4.25,2.25) 3(-4.25,1.75) 4(-4.25,1.25) 5(-4.25,0.75) 6(-4.25,0.25) 7(-4.25,-0.25) 8(-4.25,-0.75) 9(-4.25,-1.25) 10(-4.25,-1.75) 11(-4.25,-2.25) 12(-4.25,-2.75) 25(4.25,-2.75) 26(4.25,-2.25) 27(4.25,-1.75) 28(4.25,-1.25) 29(4.25,-0.75) 30(4.25,-0.25) 31(4.25,0.25) 32(4.25,0.75) 33(4.25,1.25) 34(4.25,1.75) 35(4.25,2.25) 36(4.25,2.75)
  rect 0.3x1.2 smd paste-0.1: 13(-2.75,-4.25) 14(-2.25,-4.25) 15(-1.75,-4.25) 16(-1.25,-4.25) 17(-0.75,-4.25) 18(-0.25,-4.25) 19(0.25,-4.25) 20(0.75,-4.25) 21(1.25,-4.25) 22(1.75,-4.25) 23(2.25,-4.25) 24(2.75,-4.25) 37(2.75,4.25) 38(2.25,4.25) 39(1.75,4.25) 40(1.25,4.25) 41(0.75,4.25) 42(0.25,4.25) 43(-0.25,4.25) 44(-0.75,4.25) 45(-1.25,4.25) 46(-1.75,4.25) 47(-2.25,4.25) 48(-2.75,4.25)
  silkscreen extent -3.05,-3.05 3.05,3.05, body extent -4.5,-4.5 4.5,4.5, height 1.6
MELF_SOD-80 [mil]
  rect 39x67 smd: 1(-69.5,0) 2(69.5,0)
  silkscreen extent -41,-26 42,26, body extent -73,-31 73,31, height 63
MPXV1D0630L2R2 [mil] "MPXV1D0630L2R2"
  rect 95x135 smd paste-7.87: 1(-115,0) 2(115,0)
  silkscreen extent -138,-128 138,128, body extent -142,-131 142,131, height 116
"NET TIE"#1 [mm]
  round 0.4 smd paste-5 mask+0: 1(0,0) 2(0.5,0)
  Top lines w0.4: 0.5,0 0,0
"NET TIE"#2 [mm]
  round 0.4 smd paste+0 mask+0: 1(0,0) 2(0.5,0)
  Top lines w0.4: 0,0 0.5,0
R_0402#1 [mm]
  rect 0.5x0.7 smd: 1(-0.475,0) 2(0.475,0)
  silkscreen extent -0.13,-0.35 0.13,0.35, body extent -0.51,-0.25 0.51,0.25, height 0.36
R_0402#2 [mm]
  rect 0.5x0.7 smd: 1(-0.475,0)
  rect 0.5x0.7 smd paste+0: 2(0.475,0)
  silkscreen extent -0.13,-0.35 0.13,0.35, body extent -0.51,-0.25 0.51,0.25, height 0.36
R_0508_REVERSED [mil]
  rect 30x90 smd: 1(-23,0) 2(23,0)
  silkscreen extent -4,-44 4,44, body extent -27,-40 27,42, height 28
R_1206 [mm]
  rect 0.9x1.6 smd: 1(-1.55,0) 2(1.55,0)
  silkscreen extent -1,-0.8 1,0.8, body extent -1.6,-0.83 1.6,0.83, height 0.58
"RPI - POE HOLE" [mm] "Socket Header, Pitch 2.54 mm, SMT, Vertical, dual row, 40p"
  rect 1.5x1.5 hole 1.02: 1(24.13,-1.27)
  round 1.5 hole 1.02: 2(24.13,1.27) 3(21.59,-1.27) 4(21.59,1.27) 5(19.05,-1.27) 7(16.51,-1.27) 8(16.51,1.27) 10(13.97,1.27) 11(11.43,-1.27) 12(11.43,1.27) 13(8.89,-1.27) 15(6.35,-1.27) 16(6.35,1.27) 17(3.81,-1.27) 18(3.81,1.27) 19(1.27,-1.27) 21(-1.27,-1.27) 22(-1.27,1.27) 23(-3.81,-1.27) 24(-3.81,1.27) 26(-6.35,1.27) 27(-8.89,-1.27) 28(-8.89,1.27) 29(-11.43,-1.27) 31(-13.97,-1.27) 32(-13.97,1.27) 33(-16.51,-1.27) 35(-19.05,-1.27) 36(-19.05,1.27) 37(-21.59,-1.27) 38(-21.59,1.27) 40(-24.13,1.27) GND(-24.13,-1.27) GND(-16.51,1.27) GND(-11.43,1.27) GND(-6.35,-1.27) GND(1.27,1.27) GND(8.89,1.27) GND(13.97,-1.27) GND(19.05,1.27)
  Top pour cut-out: -29,-2 -29.765,-1.848 -30.414,-1.414 -30.848,-0.765 -31,0 -31,0 -30.848,0.765 -30.414,1.414 -29.765,1.848 -29,2 -29,2 -28.235,1.848 -27.586,1.414 -27.152,0.765 -27,0 -27,0 -27.152,-0.765 -27.586,-1.414 -28.235,-1.848 -29,-2
  Top pour cut-out: -29,-51 -29.765,-50.848 -30.414,-50.414 -30.848,-49.765 -31,-49 -31,-49 -30.732,-48 -30,-47.268 -29,-47 -29,-47 -28.235,-47.152 -27.586,-47.586 -27.152,-48.235 -27,-49 -27,-49 -27.152,-49.765 -27.586,-50.414 -28.235,-50.848 -29,-51
  Top pour cut-out: 29,-2 28.235,-1.848 27.586,-1.414 27.152,-0.765 27,0 27,0 27.268,1 28,1.732 29,2 29,2 29.765,1.848 30.414,1.414 30.848,0.765 31,0 31,0 30.848,-0.765 30.414,-1.414 29.765,-1.848 29,-2
  Top pour cut-out: 29,-51 28.235,-50.848 27.586,-50.414 27.152,-49.765 27,-49 27,-49 27.268,-48 28,-47.268 29,-47 29,-47 29.765,-47.152 30.414,-47.586 30.848,-48.235 31,-49 31,-49 30.848,-49.765 30.414,-50.414 29.765,-50.848 29,-51
  Bottom pour cut-out: 29,-2 28.235,-1.848 27.586,-1.414 27.152,-0.765 27,0 27,0 27.268,1 28,1.732 29,2 29,2 29.765,1.848 30.414,1.414 30.848,0.765 31,0 31,0 30.848,-0.765 30.414,-1.414 29.765,-1.848 29,-2
  Bottom pour cut-out: -29,-2 -29.765,-1.848 -30.414,-1.414 -30.848,-0.765 -31,0 -31,0 -30.732,1 -30,1.732 -29,2 -29,2 -28.235,1.848 -27.586,1.414 -27.152,0.765 -27,0 -27,0 -27.152,-0.765 -27.586,-1.414 -28.235,-1.848 -29,-2
  Bottom pour cut-out: -29,-51 -29.765,-50.848 -30.414,-50.414 -30.848,-49.765 -31,-49 -31,-49 -30.848,-48.235 -30.414,-47.586 -29.765,-47.152 -29,-47 -29,-47 -28.235,-47.152 -27.586,-47.586 -27.152,-48.235 -27,-49 -27,-49 -27.152,-49.765 -27.586,-50.414 -28.235,-50.848 -29,-51
  Bottom pour cut-out: 29,-51 28.235,-50.848 27.586,-50.414 27.152,-49.765 27,-49 27,-49 27.268,-48 28,-47.268 29,-47 29,-47 29.765,-47.152 30.414,-47.586 30.848,-48.235 31,-49 31,-49 30.848,-49.765 30.414,-50.414 29.765,-50.848 29,-51
  Keep-Out Layer circle w0.254: c-29,-49 r2
  Keep-Out Layer circle w0.254: c29,-49 r2
  Keep-Out Layer circle w0.254: c-29,0 r2
  Keep-Out Layer circle w0.254: c29,0 r2
  silkscreen extent -30.37,-3.05 25.78,2.62, body extent -25.4,-2.51 25.35,2.49, height 8.55
SAMTEC-A-TSM-108-02-L-SH [mm]
  rect 1.27x2.8 smd: 1(-8.89,-5.283) 2(-6.35,-5.283) 3(-3.81,-5.283) 4(-1.27,-5.283) 5(1.27,-5.283) 6(3.81,-5.283) 7(6.35,-5.283) 8(8.89,-5.283)
  silkscreen extent -10.61,-7.32 10.61,9.85, body extent -10.16,-6.35 10.16,9.14, height 3.17
SAMTEC_FTSH-105-01-L-DV-K [mm]
  rect 0.74x2.79 smd: 1(-2.54,-2.035) 2(-2.54,2.035) 3(-1.27,-2.035) 4(-1.27,2.035) 5(0,-2.035) 6(0,2.035) 7(1.27,-2.035) 8(1.27,2.035) 9(2.54,-2.035) 10(2.54,2.035)
  silkscreen extent -3.74,-2.54 3.18,1.72, body extent -3.17,-2.92 3.18,2.92, height 6.11
SO-8FL [mm]
  rect 0.75x1 smd: 1(-1.905,-2.795) 2(-0.635,-2.795) 3(0.635,-2.795) 4(1.905,-2.795) 5(1.905,2.7) 6(-1.905,2.7)
  Top region: -0.94,-0.178 0.94,-0.178 0.94,1.676 -0.94,1.676
  Top region: -2.28,-1.33 2.28,-1.33 2.28,-0.905 2.775,-0.905 2.775,0 2.28,0 2.28,3.2 1.53,3.2 1.53,2.725 -1.53,2.725 -1.53,3.2 -2.28,3.2 -2.28,0 -2.775,0 -2.775,-0.905 -2.28,-0.905
  silkscreen extent -2.95,-3.45 2.92,3.35, body extent -2.57,-3.1 2.58,3.05, height 1.1
SOD-123 [mm]
  rect 1.5x2.1 smd: A(1.8,0) C(-1.8,0)
  silkscreen extent -0.56,-0.48 0.56,0.48, body extent -1.82,-0.77 1.83,0.78, height 1.44
SOT95P280X145-6N [mm]
  rrect15% 1.36x0.6 smd: 1(-1.175,0.95) 2(-1.175,0) 3(-1.175,-0.95) 4(1.175,-0.95) 5(1.175,0) 6(1.175,0.95)
  silkscreen extent -2.65,-1.57 0.81,1.57, body extent -1.4,-1.46 1.4,1.46, height 1.5
SOT-23-3 [mm]
  rect 0.8x0.9 smd: B(-0.95,-1) C(0,1) E(0.95,-1)
  silkscreen extent -1.35,-0.45 1.35,0.45, body extent -1.46,-1.22 1.46,1.25, height 1
SOT-23-THIN [mm]
  rrect5% 1.1x0.6 smd mask+0.07: 1(-1.35,0.95) 2(-1.35,0) 3(-1.35,-0.95) 4(1.35,-0.95) 5(1.35,0) 6(1.35,0.95)
  silkscreen extent -0.63,-1.25 0.62,1.04, body extent -1.4,-1.45 1.4,1.45, height 1.1
SOT-323 [mm]
  rect 0.7x0.9 smd: 1(-0.65,0) 2(0.65,0) 3(0,1.9)
  silkscreen extent -1,0.55 1,1.35, body extent -1,-0.05 1,2.05, height 0.3
SRN1060 [mm]
  rect 3.5x10.2 smd paste-5: 1(-3.3,0) 2(3.3,0)
  silkscreen extent -4.95,-5.35 4.95,5.33, body extent -5,-5 5,5, height 3.8
TESTPOINT [mm]
  round 2 smd paste+0 mask+0: 1(0,0.219)
TEXAS_INSTRUMENTS_RDA0015A_MFG [mm]
  rrect20% 1.4x0.5 smd paste-1000 mask+0: 1(-2,2.145) 7(-2,-2.155) 8(2,-2.155) 14(2,2.145)
  rrect29% 0.7x0.35 smd paste-1000 mask+0: 2(-2.35,1.17) 3(-2.35,0.52) 4(-2.35,-0.13) 5(-2.35,-0.78) 6(-2.35,-1.43) 9(2.35,-1.43) 10(2.35,-0.78) 11(2.35,-0.13) 12(2.35,0.52) 13(2.35,1.17)
  round 2.25 smd paste-1000 mask+0: 15(0,0)
  Top region: -0.75,2.3 -0.757,2.275 -0.75,2.25 -0.75,2.25 -0.75,1.3 -0.754,1.281 -0.765,1.265 -0.781,1.254 -0.8,1.25 -0.8,1.25 -1.2,1.25 -1.225,1.243 -1.243,1.225 -1.25,1.2 -1.25,1.2 -1.25,-1.2 -1.243,-1.225 -1.225,-1.243 -1.2,-1.25 -1.2,-1.25 -0.8,-1.25 -0.781,-1.254 -0.765,-1.265 -0.754,-1.281 -0.75,-1.3 -0.75,-1.3 -0.75,-2.25 -0.743,-2.275 -0.725,-2.293 -0.7,-2.3 -0.7,-2.3 0.7,-2.3 0.725,-2.293 0.743,-2.275 0.75,-2.25 0.75,-2.25 0.75,-1.3 0.754,-1.281 0.765,-1.265 0.781,-1.254 0.8,-1.25 0.8,-1.25 1.2,-1.25 1.225,-1.243 1.243,-1.225 1.25,-1.2 1.25,-1.2 1.25,1.2 1.243,1.225 1.225,1.243 1.2,1.25 1.2,1.25 0.8,1.25 0.781,1.254 0.765,1.265 0.754,1.281 0.75,1.3 0.75,1.3 0.75,2.25 0.743,2.275 0.725,2.293 0.7,2.3 0.7,2.3
  silkscreen extent -2.68,-2.8 2.55,2.93, body extent -2.8,-2.9 2.8,2.9, height 0.25
TEXAS_INSTRUMENTS_RQM0029A_MFG [mm]
  round 0.192 smd paste-0.025 mask+0: 1(-1.369,1.631)
  rrect50% 0.6x0.2 smd paste-0.025 mask+0: 2(-1.9,1.2) 3(-1.9,0.8) 4(-1.9,0.4) 5(-1.9,0) 6(-1.9,-0.4) 7(-1.9,-0.8) 8(-1.9,-1.2) 20(1.9,0) 21(1.9,0.4) 22(1.9,0.8) 23(1.9,1.2)
  round 0.158 smd paste-0.025 mask+0: 9(-1.412,-1.763)
  rrect50% 0.2x0.6 smd paste-0.025 mask+0: 10(-1,-1.9) 11(-0.6,-1.9) 12(-0.2,-1.9) 13(0.2,-1.9) 14(0.6,-1.9) 15(1,-1.9)
  round 0.175 smd paste-0.025 mask+0: 16(1.431,-1.631) 24(1.381,1.631)
  rrect50% 0.7x0.2 smd paste-0.025 mask+0: 17(1.85,-1.2)
  rrect50% 0.65x0.2 smd paste-0.025 mask+0: 18(1.875,-0.8)
  rrect50% 0.68x0.2 smd paste-0.025 mask+0: 19(1.86,-0.4)
  rrect50% 0.2x1 smd paste-0.025 mask+0: 25(0.9,1.7) 26(0.45,1.7) 27(0,1.7) 28(-0.45,1.7)
  rrect50% 0.2x0.95 smd paste-0.025 mask+0: 29(-0.9,1.725)
  Top region: -2.2,1.65 -2.193,1.675 -2.175,1.693 -2.15,1.7 -2.15,1.7 -1.45,1.7 -1.45,2.15 -1.443,2.175 -1.425,2.193 -1.4,2.2 -1.4,2.2 -1.3,2.2 -1.275,2.193 -1.257,2.175 -1.25,2.15 -1.25,2.15 -1.25,1.55 -1.254,1.531 -1.265,1.515 -1.281,1.504 -1.3,1.5 -1.3,1.5 -2.15,1.5 -2.169,1.504 -2.185,1.515 -2.196,1.531 -2.2,1.55 -2.2,1.55
  Top region: -2.2,-1.65 -2.193,-1.675 -2.175,-1.693 -2.15,-1.7 -2.15,-1.7 -1.5,-1.7 -1.5,-2.15 -1.496,-2.169 -1.485,-2.185 -1.469,-2.196 -1.45,-2.2 -1.45,-2.2 -1.35,-2.2 -1.331,-2.196 -1.315,-2.185 -1.304,-2.169 -1.3,-2.15 -1.3,-2.15 -1.3,-1.55 -1.304,-1.531 -1.315,-1.515 -1.331,-1.504 -1.35,-1.5 -1.35,-1.5 -2.15,-1.5 -2.169,-1.504 -2.185,-1.515 -2.196,-1.531 -2.2,-1.55 -2.2,-1.55
  Top region: 2.2,-1.65 2.193,-1.675 2.175,-1.693 2.15,-1.7 2.15,-1.7 1.5,-1.7 1.5,-2.15 1.496,-2.169 1.485,-2.185 1.469,-2.196 1.45,-2.2 1.45,-2.2 1.35,-2.2 1.325,-2.193 1.307,-2.175 1.3,-2.15 1.3,-2.15 1.3,-1.55 1.304,-1.531 1.315,-1.515 1.331,-1.504 1.35,-1.5 1.35,-1.5 2.15,-1.5 2.169,-1.504 2.185,-1.515 2.196,-1.531 2.2,-1.55 2.2,-1.55
  Top region: 2.2,1.65 2.196,1.669 2.185,1.685 2.169,1.696 2.15,1.7 2.15,1.7 1.45,1.7 1.45,2.15 1.446,2.169 1.435,2.185 1.419,2.196 1.4,2.2 1.4,2.2 1.3,2.2 1.275,2.193 1.257,2.175 1.25,2.15 1.25,2.15 1.25,1.55 1.254,1.531 1.265,1.515 1.281,1.504 1.3,1.5 1.3,1.5 2.15,1.5 2.169,1.504 2.185,1.515 2.196,1.531 2.2,1.55 2.2,1.55
  silkscreen extent -2.42,-2.3 2.3,2.42, body extent -2.3,-2.3 2.3,2.3, height 0.25
VQFN32 [mm]
  rrect10% 0.6x0.2 smd paste-0.025 mask+0.05: 1(-1.9,1.4) 2(-1.9,1) 3(-1.9,0.6) 4(-1.9,0.2) 5(-1.9,-0.2) 6(-1.9,-0.6) 7(-1.9,-1) 8(-1.9,-1.4) 17(1.9,-1.4) 18(1.9,-1) 19(1.9,-0.6) 20(1.9,-0.2) 21(1.9,0.2) 22(1.9,0.6) 23(1.9,1) 24(1.9,1.4)
  rrect10% 0.2x0.6 smd paste-0.025 mask+0.05: 9(-1.4,-1.9) 10(-1,-1.9) 11(-0.6,-1.9) 12(-0.2,-1.9) 13(0.2,-1.9) 14(0.6,-1.9) 15(1,-1.9) 16(1.4,-1.9) 25(1.4,1.9) 26(1,1.9) 27(0.6,1.9) 28(0.2,1.9) 29(-0.2,1.9) 30(-0.6,1.9) 31(-1,1.9) 32(-1.4,1.9)
  rrect10% 1.4x1.4 smd paste-0.025 mask+0.05: 33(0,0)
  silkscreen extent -2.09,-2 2,2.09, body extent -2.08,-2.08 2.08,2.08, height 0.8
WCAP-ASLI_D6.3H5.5 [mm] "Aluminium Electrolytic V-Chip SMT Capacitors, 6.3x5.5mm"
  rect 3.5x1.6 smd: 1(2.8,0) 2(-2.8,0)
  silkscreen extent -3.4,-3.4 3.4,3.4, body extent -3.65,-3.3 3.65,3.3, height 5.5
WE-LQS_4012 [mm] "SMD Power Inductor, 2-Leads, body 4x4mm"
  rect 1.5x3.6 smd: 1(-1.525,0) 2(1.525,0)
  silkscreen extent -2.1,-2.1 2.1,2.1, body extent -2,-2 2,2, height 1.19
WE-XTAL_IQXC-26 [mm] "Quartz Crystal, size IQXC-26, body 1.6x1.2mm"
  rect 0.6x0.5 smd: 1(-0.55,-0.4) 2(0.55,-0.4) 3(0.55,0.4) 4(-0.55,0.4)
  silkscreen extent -1.2,-0.45 -1.1,-0.35, body extent -0.8,-0.6 0.8,0.6, height 0.4
WL-SBSW_1204 [mm] "SMD Bi-color Side view Waterclear, body 3.2x1mm"
  rect 0.9x0.7 smd: 1(0,-0.91)
  rect 1.2x0.7 smd: 2(1.5,-0.51) 3(-1.5,-0.51)
  silkscreen extent -0.98,0.04 0.98,0.75, body extent -1.6,-0.76 1.6,0.74, height 1.02
X_USBC_JACK [mm] "10137065-00021LF"
  rect 0.27x0.9 smd: A01(-2.625,2.875) A02(-2.125,2.875) A03(-1.625,2.875) A04(-1.125,2.875) A05(-0.625,2.875) A06(-0.125,2.875) A07(0.375,2.875) A08(0.875,2.875) A09(1.375,2.875) A10(1.875,2.875) A11(2.375,2.875) A12(2.875,2.875) B01(2.625,1.225) B02(2.125,1.225) B03(1.625,1.225) B04(1.125,1.225) B05(0.625,1.225) B06(0.125,1.225) B07(-0.375,1.225) B08(-0.875,1.225) B09(-1.375,1.225) B10(-1.875,1.225) B11(-2.375,1.225) B12(-2.875,1.225) B12(-2.875,1.225)
  oval 1.3x2.6 hole 0.7 slot 2 at 90 deg mask+0.102: ""(-4.32,-2.875)
  oval 1.2x2.3 hole 0.6 slot 1.9 at 90 deg mask+0.102: ""(-4.32,2.175) ""(4.32,2.175)
  oval 1.45x1.1 hole 0.7 slot 1.25 at 0 deg mask+0.102: ""(-3.995,1.575)
  round 0 hole 0.6 unplated mask+0.102: ""(-3.6,0.175)
  round 0 hole 0.5 slot 0.85 at 0 deg unplated mask+0.102: ""(3.6,0.24)
  oval 1.45x1.1 hole 0.7 slot 1.25 at 0 deg: ""(3.995,1.575)
  oval 1.3x2.6 hole 0.7 slot 2 at 90 deg: ""(4.32,-2.875)
  Keep-Out Layer region: -3.9,-4.675 3.9,-4.675 3.9,-0.2 -3.9,-0.2
  body extent -4.49,-5.1 4.45,3.05, height 3.17
X_XH5 [mm]
  rrect25% 1.9x1.9 hole 0.9: 1(-5,0) 2(-2.5,0) 3(0,0) 4(2.5,0) 5(5,0)
  silkscreen extent -7.45,-1.36 7.45,7.23, body extent -7.52,-0.4 7.48,7.24, height 5.95
X_XT30_90° [mm]
  rect 3.4x3.4 hole 1.7: 1(-2.5,-5)
  round 3.4 hole 1.7: 2(2.5,-5)
  round 2 hole 1: ""(-5.5,5) ""(5.5,5)
  silkscreen extent -6.71,-5.92 6.71,7.98, body extent -6.65,-6 6.65,7.95, height 5
XTAL_NX2012SA-32.768K-STD-MUB-1 [mm]
  rect 1x1.25 smd: 1(-0.75,0) 2(0.75,0)
  silkscreen extent -0.15,-0.63 0.15,0.62, body extent -1.1,-0.6 1.1,0.6, height 0.55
